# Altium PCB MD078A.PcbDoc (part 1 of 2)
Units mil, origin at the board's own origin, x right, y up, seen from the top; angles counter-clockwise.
Board outline 4255 x 2850 mil, 4 copper layers (Top Layer, Ground, Power, Bottom Layer), stack 61.6 mil thick; 156 components, 78 nets, 386 pads, 377 vias.
Unrouted connection lines stored in the file: 8.
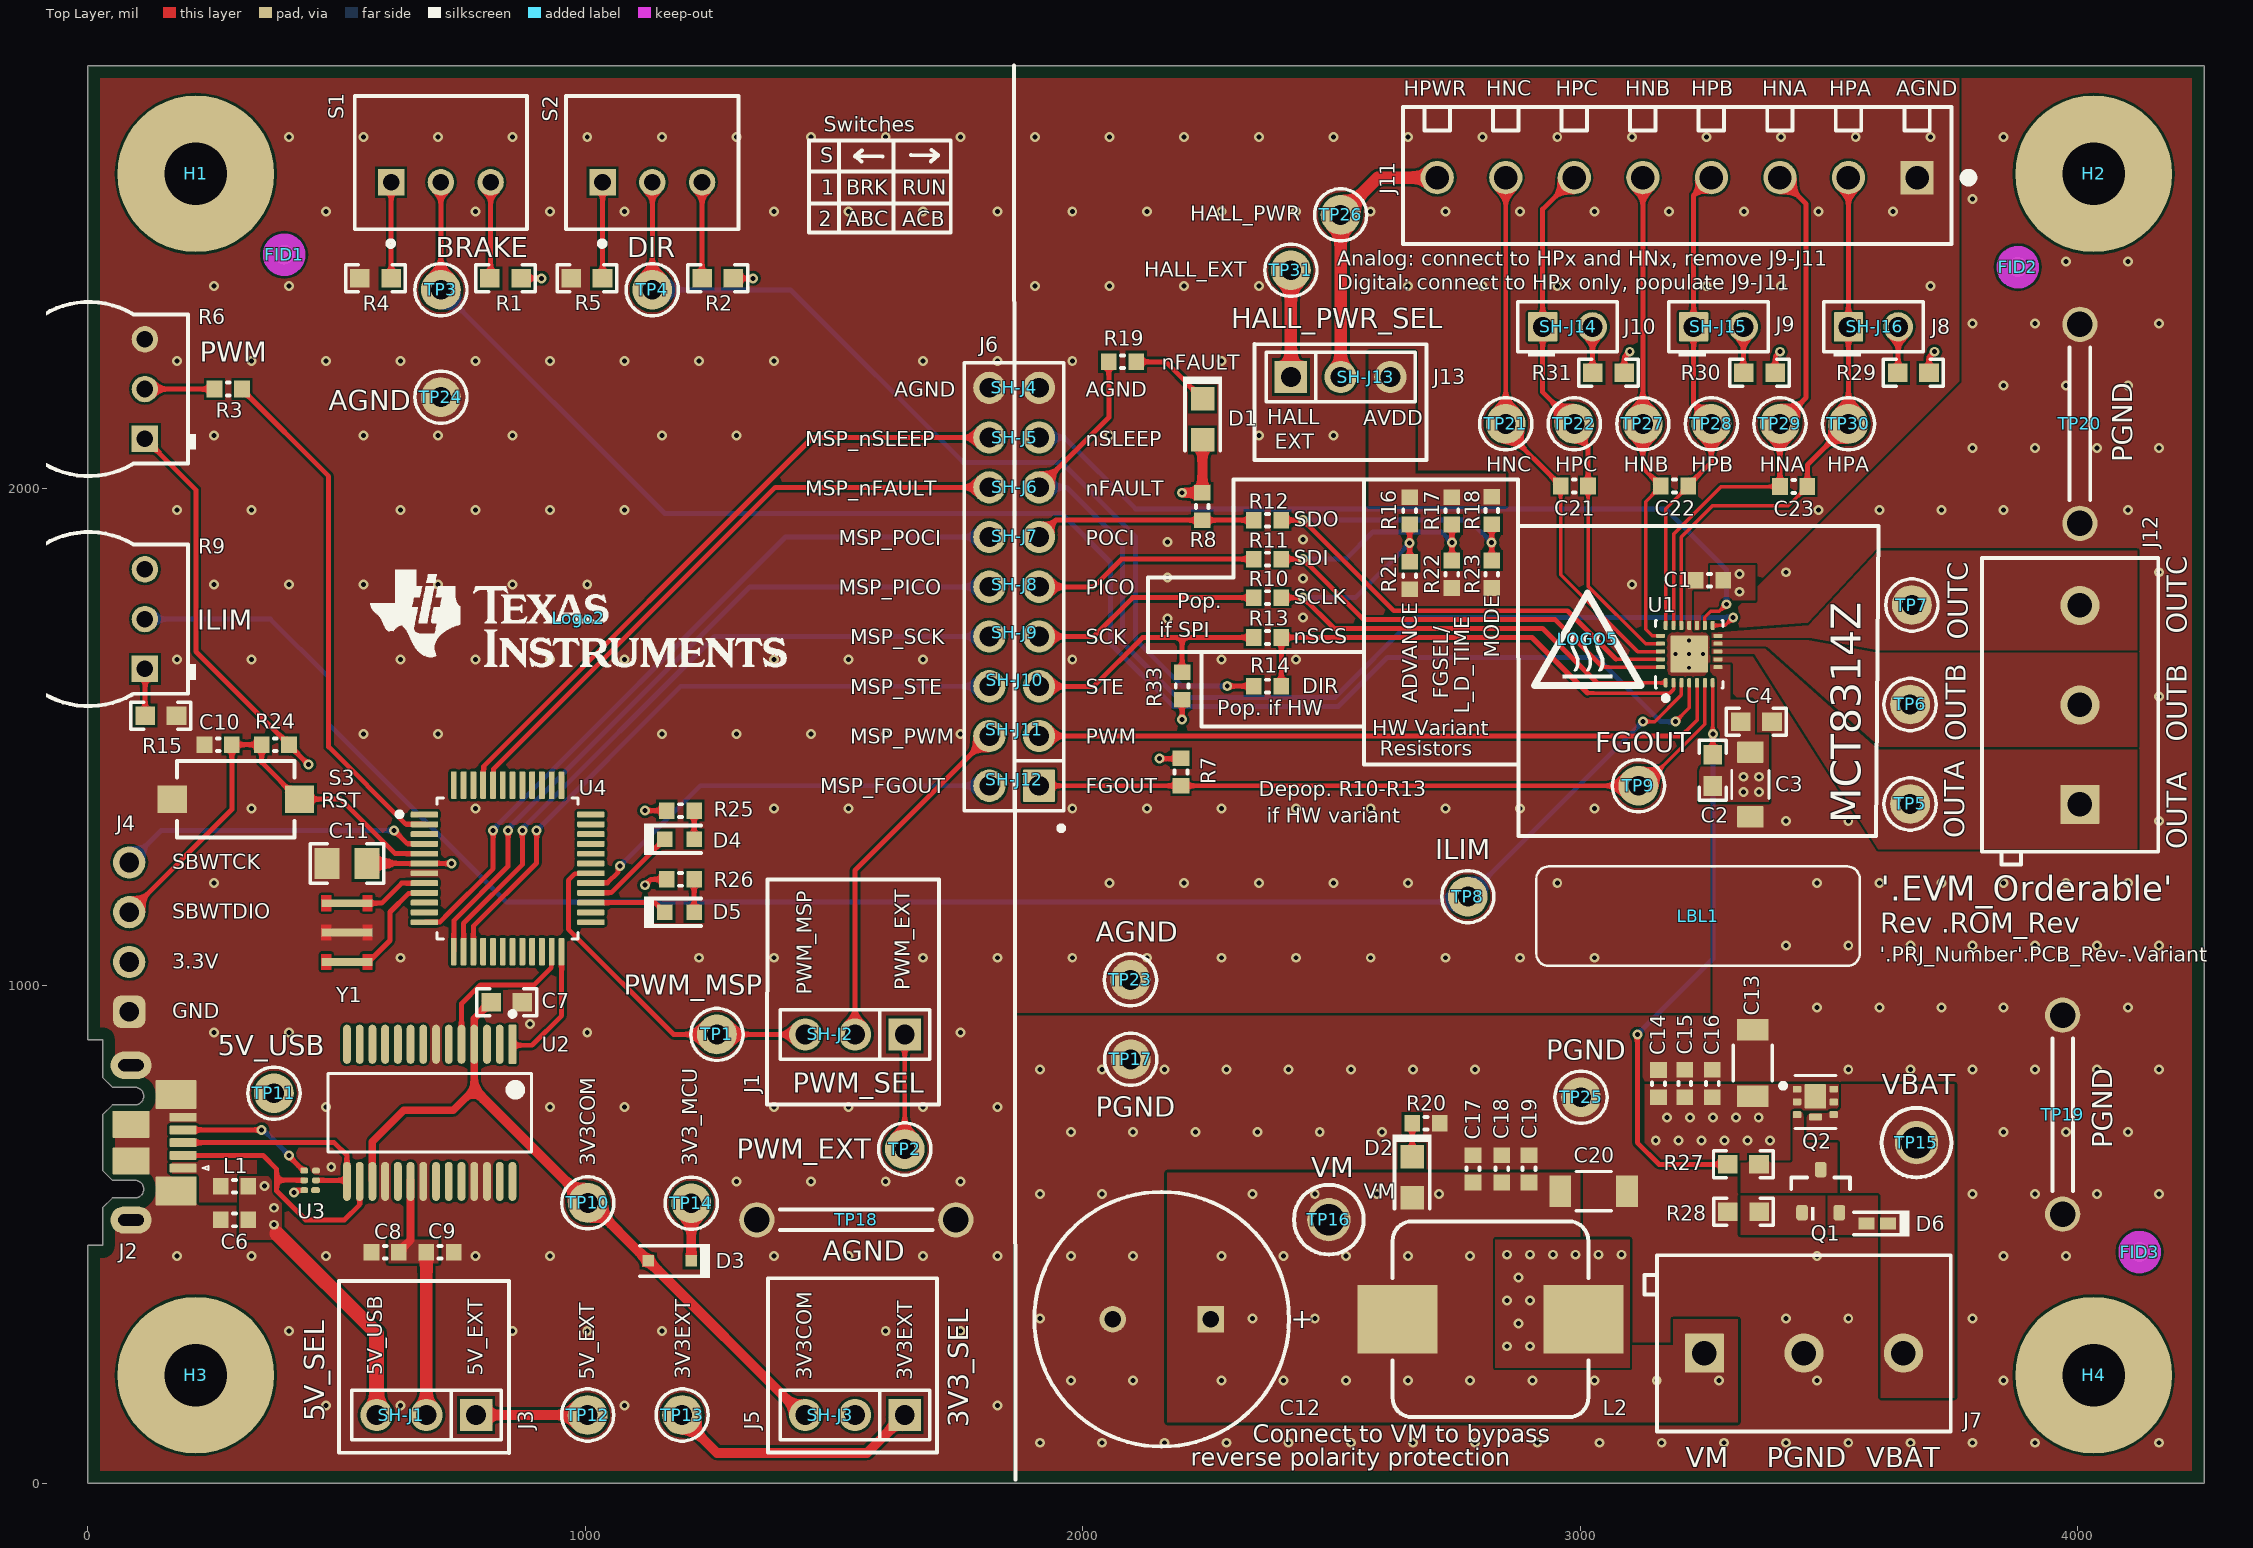
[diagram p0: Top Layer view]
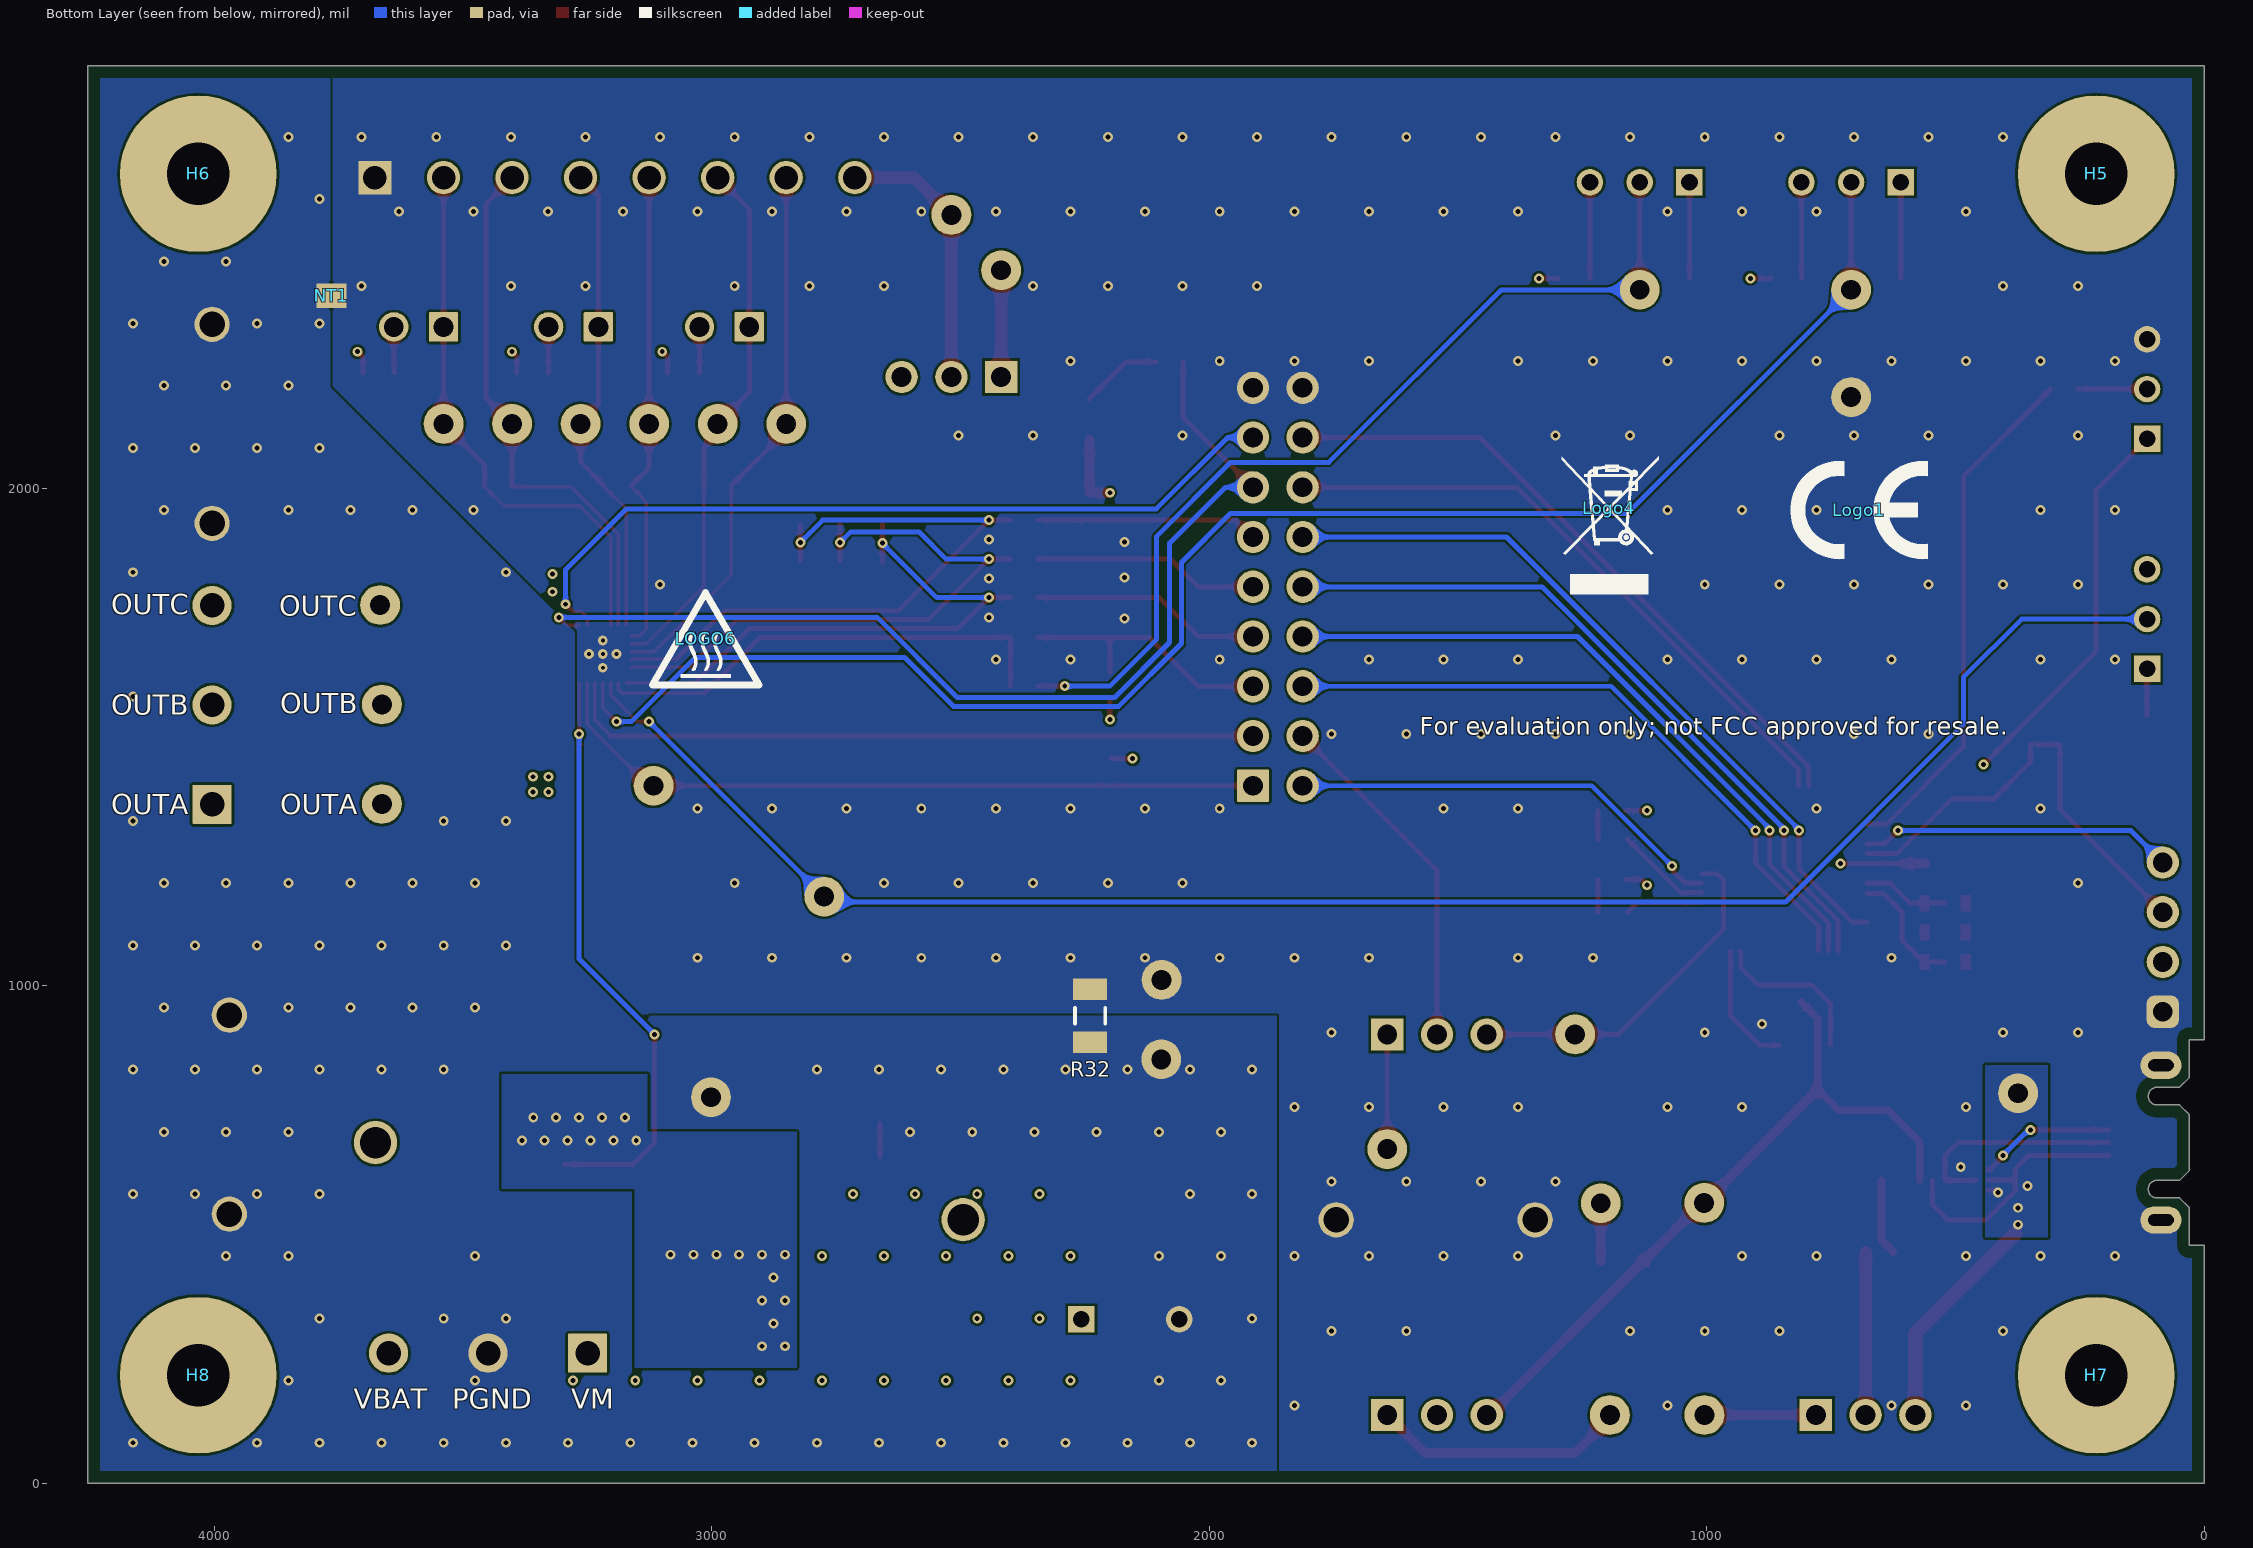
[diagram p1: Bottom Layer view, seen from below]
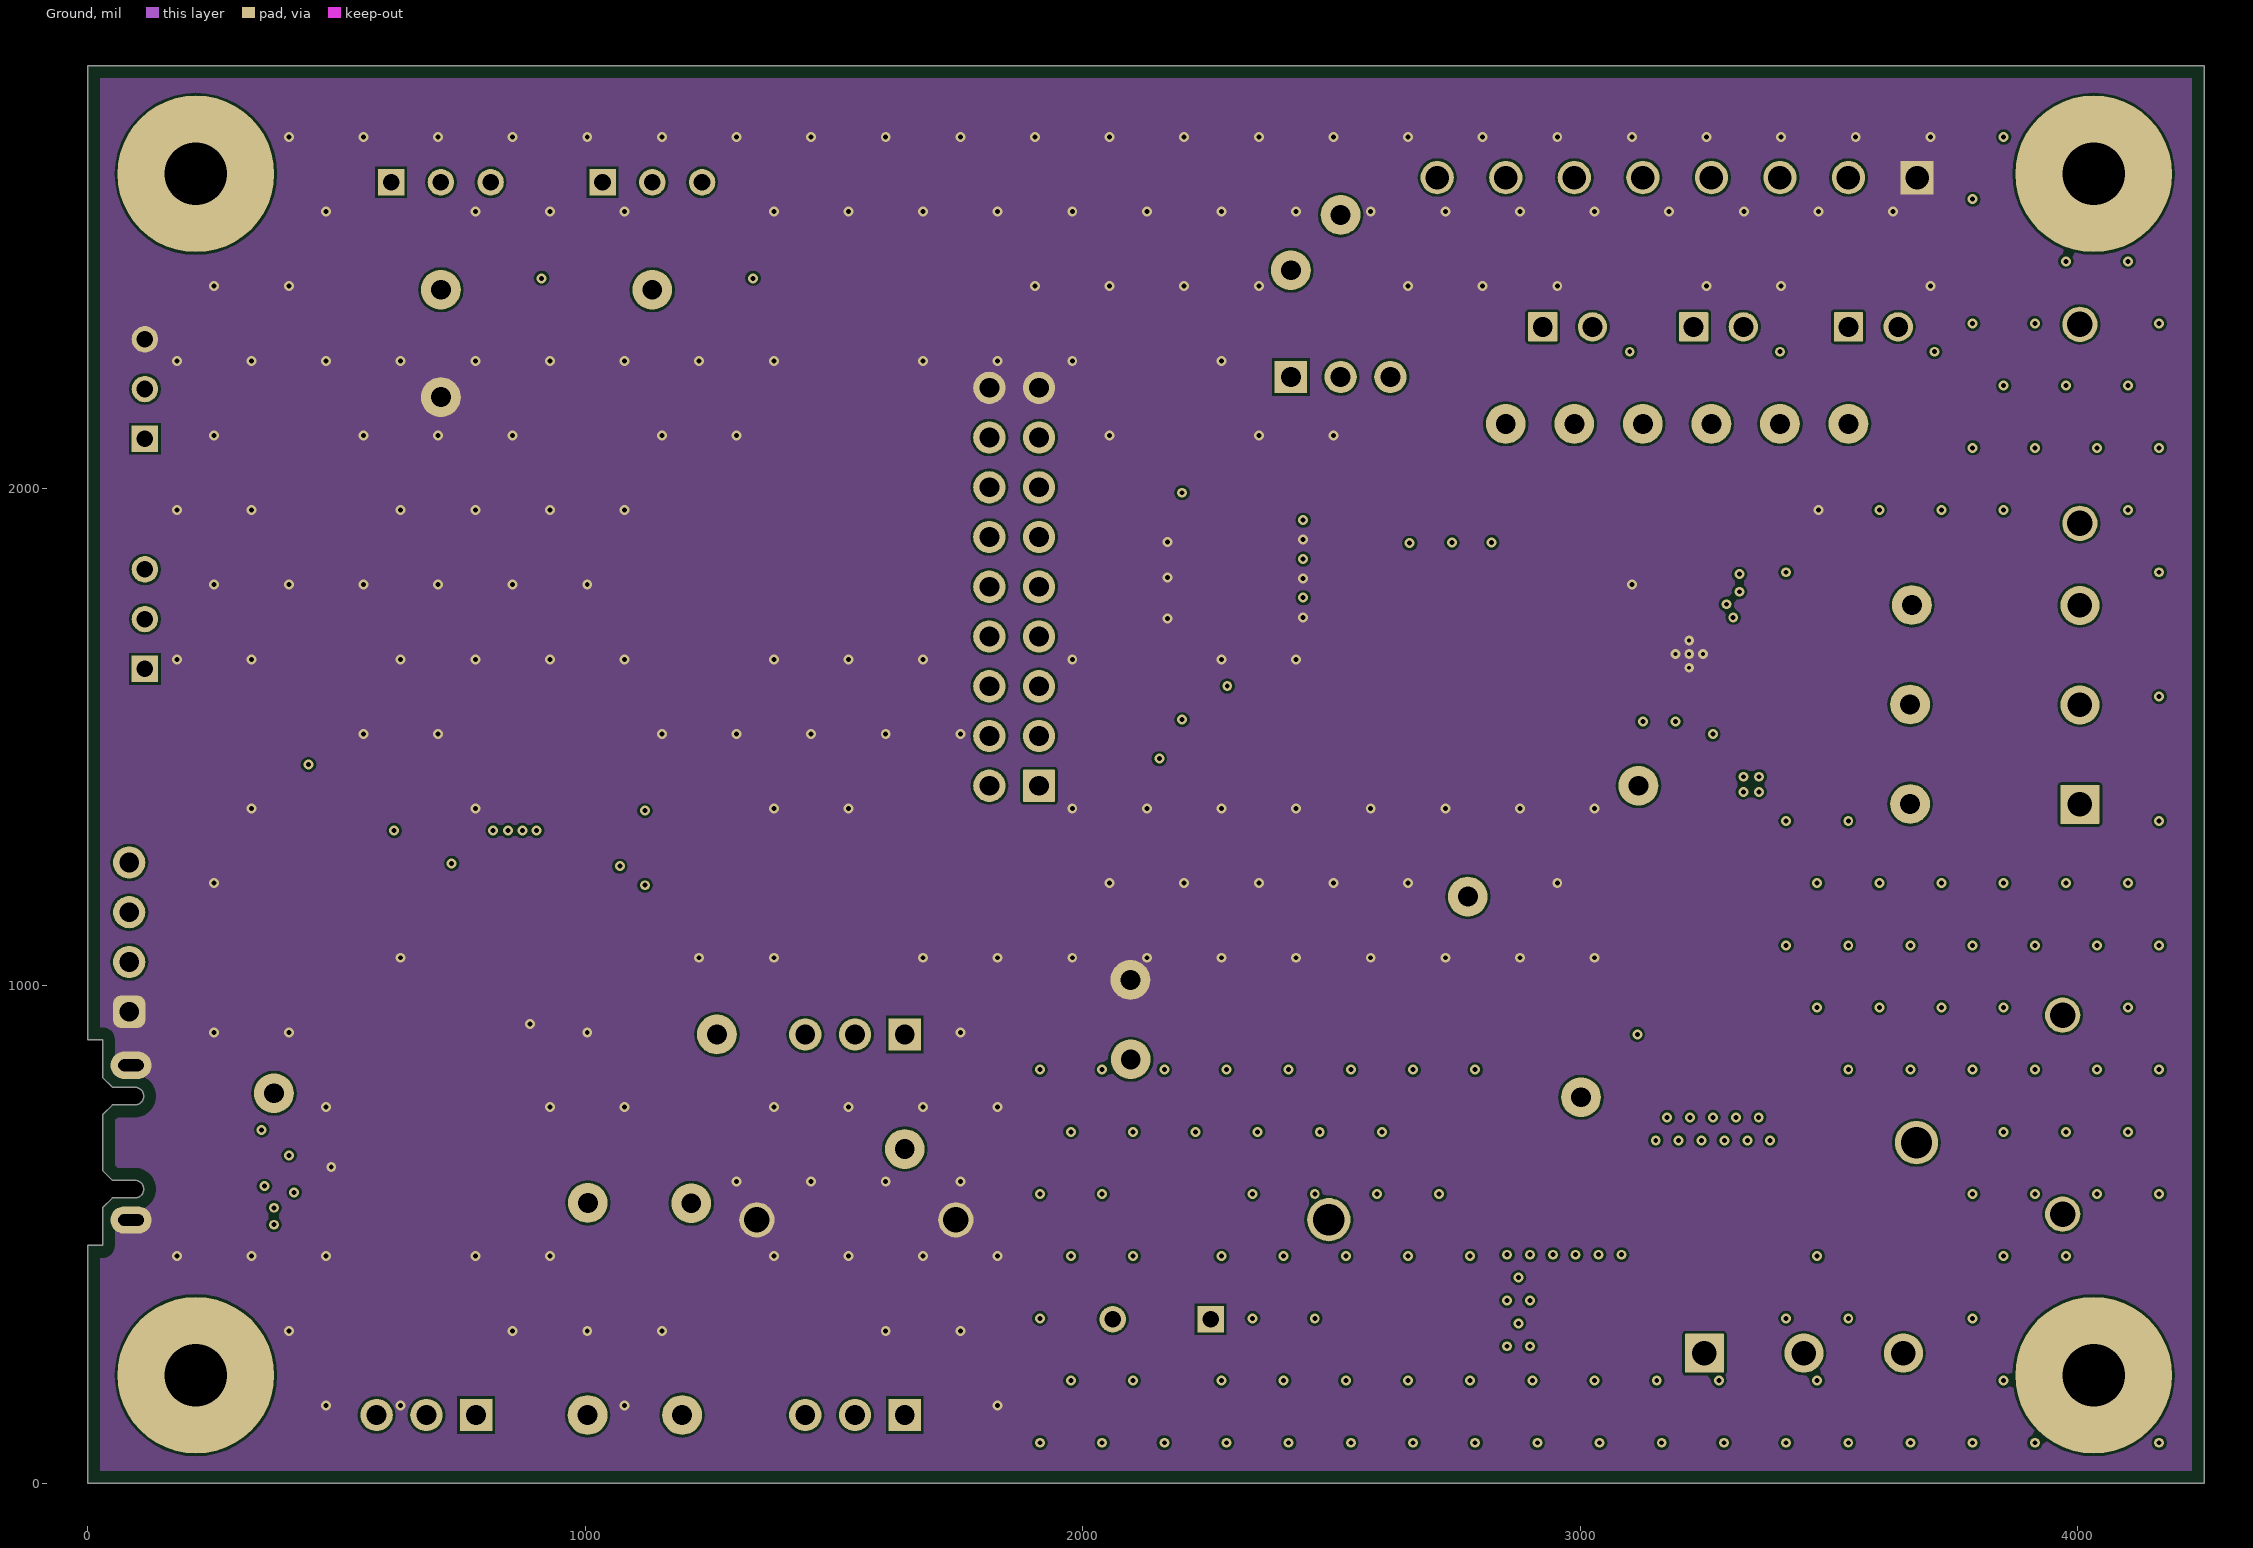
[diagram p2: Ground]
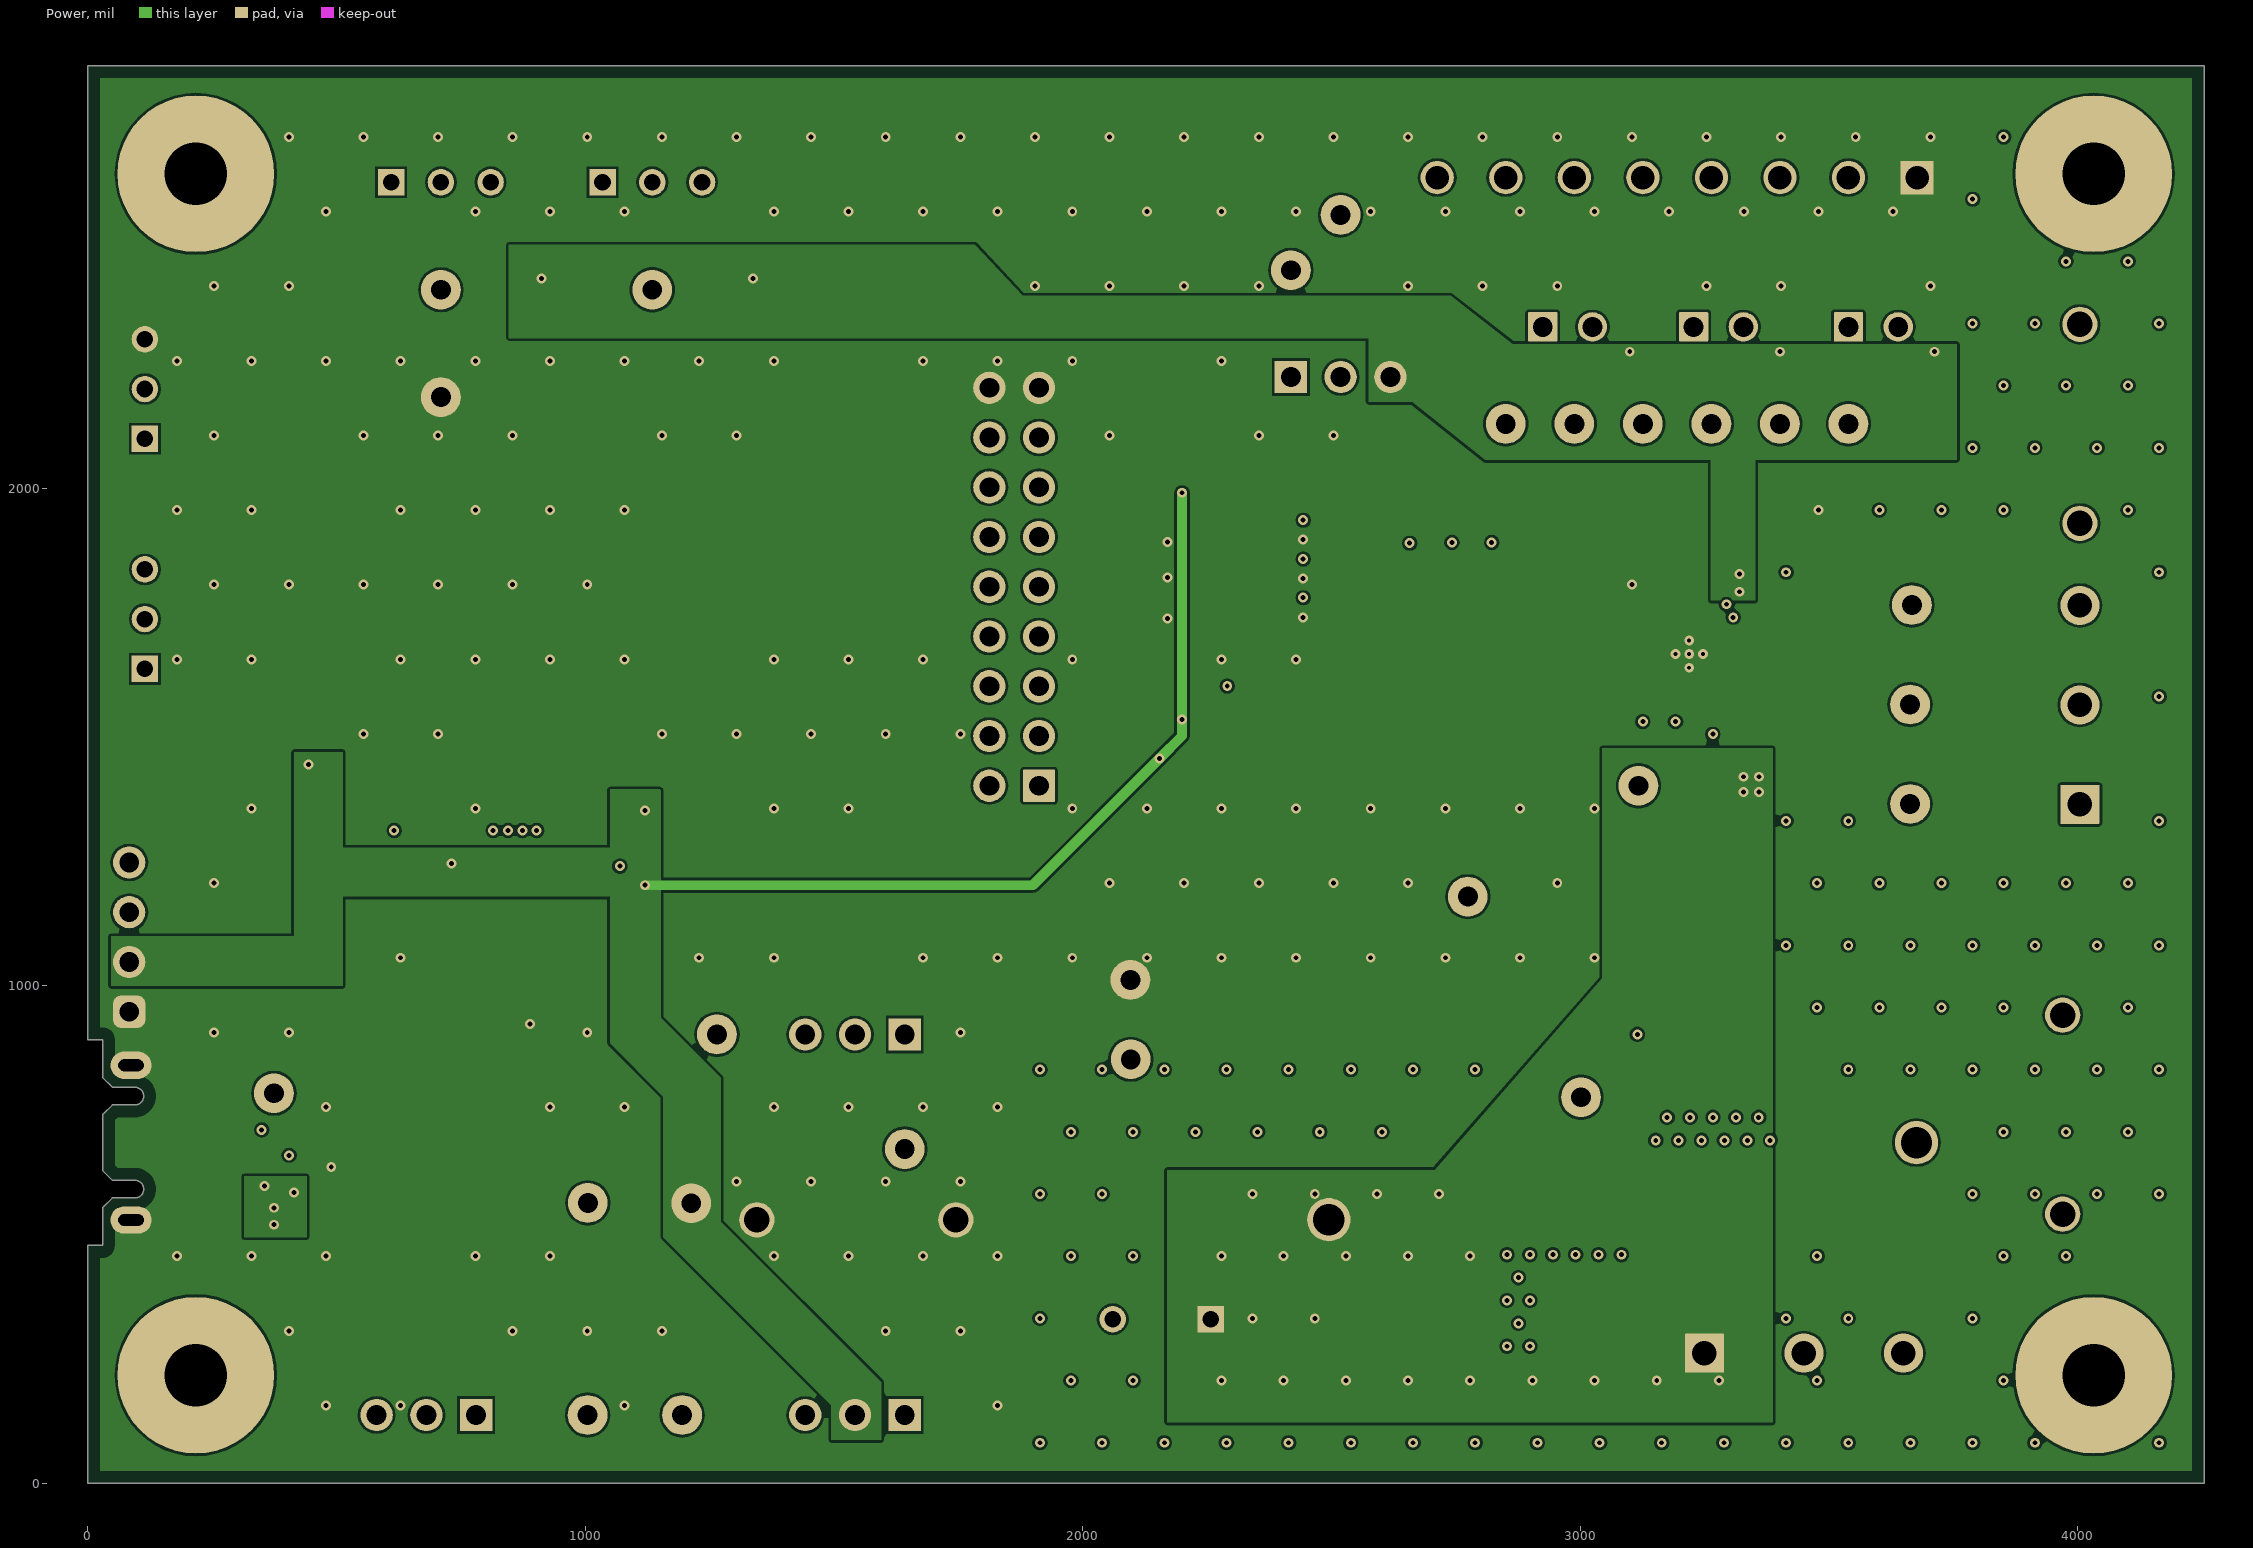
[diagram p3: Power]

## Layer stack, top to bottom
Top Solder: solder mask 0.4, Solder Resist, Dk 3.5
Top Layer: signal copper 1.4
Dielectric 1: prepreg 8, FR-4, Dk 4.2
Ground: signal copper 1.4
Dielectric 2: core 40, FR-4, Dk 4.2
Power: signal copper 1.4
Dielectric 3: prepreg 8, FR-4, Dk 4.2
Bottom Layer: signal copper 1.4
Bottom Solder: solder mask 0.4, Solder Resist, Dk 3.5

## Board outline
0,478.31 30,478.31 30,554.09 49.68,573.78 94.96,573.78 ccw(c94.85,591.5) 94.96,609.21 49.68,609.21 30,628.9 30,741.1 49.68,760.79 94.96,760.79 ccw(c94.85,778.5) 94.96,796.22 49.68,796.22 30,815.91 30,891.69 0,891.69 0,2850 4255,2850 4255,0 0,0

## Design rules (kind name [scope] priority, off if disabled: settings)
AcuteAngle [All] p1: minimum=4.50000000000000E+0001 checktracksonly=FALSE
AssemblyTestPointUsage [All] p1: valid=2
BoardOutlineClearance BoardOutlineClearance_1 [HasFootprint('Molex_1051640001')] p1: gap=0 ignorepadtopadclearanceinfootprint=FALSE
BoardOutlineClearance BoardOutlineClearance_MountingHoles [OnCopper and InComponentClass('Mounting Holes')] p2: gap=39.37 ignorepadtopadclearanceinfootprint=FALSE
BoardOutlineClearance BoardOutlineClearance_Poly [OnCopper and IsPoly] p3: gap=25 ignorepadtopadclearanceinfootprint=FALSE
BoardOutlineClearance [OnCopper and Not InComponentClass('Logo') and not InComponentClass('FiducialMark') and not InRegion(1000,500,4000,800) and not InPoly] p4: gap=30 ignorepadtopadclearanceinfootprint=FALSE
Clearance Clearance_Keepouts [((IsTrack Or IsArc) And Not InPoly) And IsFree and IsKeepOut vs ((IsTrack Or IsArc) And Not InPoly) And IsFree and IsKeepOut] p1: gap=0 ignorepadtopadclearanceinfootprint=FALSE
Clearance Clearance_Poly [InPolygon] p2: gap=5 ignorepadtopadclearanceinfootprint=TRUE
Clearance Clearance_FiducialMark [IsKeepOut and InComponentClass('FiducialMark') vs IsPad and InComponentClass('FiducialMark')] p3: gap=0 ignorepadtopadclearanceinfootprint=FALSE
Clearance [All] p4: gap=7.87 ignorepadtopadclearanceinfootprint=TRUE
ComponentClearance ComponentClearance_MountingHoles_FiducialMarks [InComponentClass('Mounting Holes') vs InComponentClass('FiducialMark')] p1: gap=50 collisioncheckmode=3 verticalgap=10 showdistances=FALSE
ComponentClearance ComponentClearance_Shunt [InComponentClass('Header') vs InComponentClass('Shunt')] p2: gap=0 collisioncheckmode=3 verticalgap=0 showdistances=FALSE
ComponentClearance ComponentClearance_Logo [InComponentClass('Logo')] p3: gap=50 collisioncheckmode=3 verticalgap=10 showdistances=FALSE
ComponentClearance ComponentClearance_ScrewToNut [(HasFootprint('NY PMS 440 0025 PH')) vs (HasFootprint('Keystone_1902C'))] p4: gap=5 collisioncheckmode=3 verticalgap=10 showdistances=FALSE
ComponentClearance ComponentClearance_MountingHoles [InComponentClass('Mounting Holes')] p5: gap=150 collisioncheckmode=3 verticalgap=100000 showdistances=FALSE
ComponentClearance ComponentClearance_SmallPassives [HasFootprint('0201*') or HasFootprint('0402*') or HasFootprint('0508') or HasFootprint('0603*') or HasFootprint('0612') or HasFootprint('0805*') or HasFootprint('0815*') or HasFootprint('0830*') or HasFootprint('1206*') or HasFootprint('1210*') or HasFootprint('1808*') or HasFootprint('1812*') or HasFootprint('1825*') or HasFootprint('2010*') or HasFootprint('2220*') or HasFootprint('2225*') or HasFootprint('2512*') or HasFootprint('2728*') or HasFootprint('3518*') vs HasFootprint('0201*') or HasFootprint('0402*') or HasFootprint('0508') or HasFootprint('0603*') or HasFootprint('0612') or HasFootprint('0805*') or HasFootprint('0815*') or HasFootprint('0830*') or HasFootprint('1206*') or HasFootprint('1210*') or HasFootprint('1808*') or HasFootprint('1812*') or HasFootprint('1825*') or HasFootprint('2010*') or HasFootprint('2220*') or HasFootprint('2225*') or HasFootprint('2512*') or HasFootprint('2728*') or HasFootprint('3518*')] p6: gap=14.96 collisioncheckmode=3 verticalgap=10 showdistances=FALSE
ComponentClearance ComponentClearance_THtoSMT [IsThruComponent vs IsSMTComponent] p7: gap=0 collisioncheckmode=3 verticalgap=0 showdistances=FALSE
ComponentClearance ComponentClearance_THtoTH [IsThruComponent vs IsThruComponent] p8: gap=0 collisioncheckmode=3 verticalgap=0 showdistances=FALSE
ComponentClearance [All] p9: gap=0 collisioncheckmode=3 verticalgap=0 showdistances=FALSE
DiffPairsRouting [All] p1: maxlimit=100 minlimit=10 mostfreqgap=10 toplayer_minwidth=10 toplayer_maxwidth=15 toplayer_prefwidth=15 midlayer1_minwidth=10 midlayer1_maxwidth=15 midlayer1_prefwidth=15 midlayer2_minwidth=10 midlayer2_maxwidth=15 midlayer2_prefwidth=15 bottomlayer_minwidth=10 bottomlayer_maxwidth=15 bottomlayer_prefwidth=15 maxuncoupledlength=1000
FabricationTestPointUsage TestPointUsage [All] p1: valid=2 allowmultiple=FALSE
FabricationTestpoint Testpoint [All] p1: side=3 testpointundercomponent=TRUE minsize=40 maxsize=100 preferedsize=60 minholesize=0 maxholesize=40 preferedholesize=32 testpointgrid=1 allowsidetop=TRUE allowsidebottom=TRUE usegrid=TRUE gridtolerance=0.01
FanoutControl Fanout_LCC [IsLCC] p1: bgadir=Out bgaviamode=Centered fanoutstyle=Auto fanoutdirection=Alternating viagrid=1 // Fanout_LCC (Default Rule)
FanoutControl Fanout_BGA [IsBGA] p2: bgadir=Out bgaviamode=Centered fanoutstyle=Auto fanoutdirection=Alternating viagrid=1 // Fanout_BGA (Default Rule)
FanoutControl Fanout_Default [All] p4: bgadir=Out bgaviamode=Centered fanoutstyle=Auto fanoutdirection=Alternating viagrid=1 // Fanout_Default (Default Rule)
FanoutControl Fanout_Small [(CompPinCount < 5)] p5: bgadir=Out bgaviamode=Centered fanoutstyle=Auto fanoutdirection=OutThenIn viagrid=1 // Fanout_Small (Default Rule)
HoleSize [All] p1: absolutevalues=TRUE maxlimit=200 minlimit=1 maxpercent=80.000 minpercent=20.000
MinimumAnnularRing MinimumAnnularRing_ThermalPadVias [IsVia and InAnyComponent] p1: minimumring=1
MinimumAnnularRing [All] p2: minimumring=1
MinimumSolderMaskSliver MinimumSolderMaskSliver_Logo [InComponentClass('Logo') vs InComponentClass('Logo')] p1: minsoldermaskwidth=0.7
MinimumSolderMaskSliver [All] p2: minsoldermaskwidth=1
PlaneConnect [All] p1: planeconnectstyle=Relief reliefexpansion=10 reliefentries=4 reliefconductorwidth=10 reliefairgap=10
PolygonConnect [All] p1: connectstyle=Direct reliefconductorwidth=10 reliefentries=4 polygonreliefangle="90 Angle" airgapwidth=10
RoutingVias ThermalPadVias [IsVia and InAnyComponent] p1: holewidth=7.87 width=19.68 viastyle="Through Hole" minholewidth=7.87 minwidth=19.68 maxholewidth=12.99 maxwidth=23.62
RoutingVias [All] p2: holewidth=10 width=25 viastyle="Through Hole" minholewidth=7 minwidth=20 maxholewidth=15 maxwidth=30
SilkToBoardRegionClearance [Not ((IsComment or IsDesignator) And (Hide <> 'False')) and not InRegion(1000,500,4000,800)] p1:
SilkToSilkClearance SilkToSilkClearance_Pb-FreeLogo [(HasFootprint('Pb-Free_Overlay_Medium') OR HasFootprint('Pb-Free_Overlay_Small')) vs (HasFootprint('Pb-Free_Overlay_Medium') OR HasFootprint('Pb-Free_Overlay_Small'))] p1: silktosilkclearance=1
SilkToSilkClearance [All] p2: silktosilkclearance=1
SilkToSolderMaskClearance [IsPad] p1: minsilkscreentomaskgap=1 clearancetoexposedcopper=TRUE
SolderMaskExpansion [All] p1: expansion=1.97 istentingtop=FALSE
UnRoutedNet [All] p1: checkbadconnections=TRUE
Width [All] p1: maxlimit=100 minlimit=6 preferedwidth=10 checkconnectedcopper=TRUE
14 further rules are at their usual default settings.

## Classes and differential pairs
component class Label: LBL1
component class "Mounting Holes": H1 H2 H3 H4
component class MD078A_INTERFACE: 3V3_EXT C6 C7 C8 C9 C10 C11 D3 D4 D5 J2 J3 J4 J5 J6 L1 R24 R25 R26 S3 SH-J2 SH-J3 SH-J4 SH-J5 SH-J6 SH-J7 SH-J8 SH-J9 SH-J10 SH-J11 SH-J12 TP10 TP11 TP12 TP13 TP14 U2 U3 U4 Y1
component class MD078A_CONTROL: J1 R1 R2 R3 R4 R5 R6 S1 S2 SH-J1 TP1 TP2 TP3 TP4
component class Shunt: SH-J1 SH-J2 SH-J3 SH-J4 SH-J5 SH-J6 SH-J7 SH-J8 SH-J9 SH-J10 SH-J11 SH-J12 SH-J13 SH-J14 SH-J15 SH-J16
component class MD078A_POWER_AND_CONNECTORS: AGND1 C12 C13 C14 C15 C16 C17 C18 C19 C20 C21 C22 C23 D6 J7 J8 J9 J10 J11 J12 J13 L2 NT1 PGND PGND2 Q1 Q2 R27 R28 R29 R30 R31 R32 R45 SH-J13 SH-J14 SH-J15 SH-J16 TP15 TP16 TP17 TP18 TP19 TP20 TP21 TP22 TP23 TP24 TP25 TP26 TP27 TP28 TP29 TP30 TP31 vm VM1
component class MD078A_DRIVER: 1 A1 B1 C1 C2 C3 C4 D1 D2 D? ILIM1 R7 R8 R9 R10 R11 R12 R13 R14 R15 R16 R17 R18 R19 R20 R21 R22 R23 R33 TP5 TP6 TP7 TP8 TP9 U1
component class Header: J1 J3 J4 J5 J6 J8 J9 J10 J13
component class Logo: Logo2
component class MD078A_HARDWARE: FID1 FID2 FID3 H1 H2 H3 H4 H5 H6 H7 H8 LBL1 Logo1 Logo2 Logo3 Logo4 LOGO5 LOGO6 ZZ1 ZZ2 ZZ3 ZZ4
component class FiducialMark: FID1 FID2 FID3
component class AssemblyNote: ZZ1 ZZ2 ZZ3 ZZ4

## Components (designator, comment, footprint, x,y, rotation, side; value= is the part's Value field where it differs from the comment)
C1 "GRM188Z71C225KE43" 0603L 3260.43,1815.47 r180 top value=2.2uF
C2 "C0603C224K4RACTU" 0603 3266.91,1433.54 r90 top value=0.22uF
C3 "C3216X6S2A106K160AC" FP-C3216X6S2A106K160AC_1206-MFG 3342.44,1405 r90 top value=10µF
C4 "GCJ188R72A104KA01D" 0603 3354.41,1531.45 r0 top value=0.1uF
C6 "C0603C104K8RACTU" 0603L 295.3,529.83 r180 top value=0.1uF
C7 "C0603C104K8RACTU" 0603 842.5,967.5 r0 top value=0.1uF
C8 "GRM188Z71A475ME15D" 0603L 597.93,464.83 r0 top value=4.7uF
C9 "C0603C104K8RACTU" 0603L 708.38,464.83 r0 top value=0.1uF
C10 "885012206034" 0603L 262.36,1485.08 r180 top value=1000pF
C11 "C0805C105K5RACTU" 0805_HV 521.16,1246.18 r180 top value=1uF
C12 "ELXZ630ELL331MK20S" Chemi-Con_1250x2000 2159.07,330 r180 top value=330uF
C13 "GRM31CR72A105KA01L" 1206_180 3347.22,845.06 r90 top value=1uF
C14 "CGA3E3X7S2A104K080AB" 0603L 3157.89,803.52 r90 top value=0.1uF
C15 "CGA3E2X7R2A103K080AA" 0603L 3210.43,803.77 r90 top value=0.01uF
C16 "06031C102JAT2A" 0603L 3266.18,803.88 r90 top value=1000pF
C17 "06031C102JAT2A" 0603L 2785,632.45 r90 top value=1000pF
C18 "CGA3E2X7R2A103K080AA" 0603L 2842.95,632.45 r90 top value=0.01uF
C19 "CGA3E3X7S2A104K080AB" 0603L 2897.5,632.45 r90 top value=0.1uF
C20 "GRM31CR72A105KA01L" 1206_180 3027.5,587.55 r0 top value=1uF
C21 "0603YC104K4T4A" 0603L 2988.52,2005 r0 top value=0.1uF
C22 "0603YC104K4T4A" 0603L 3189.74,2005 r0 top value=0.1uF
C23 "0603YC104K4T4A" 0603L 3429.47,2004.02 r0 top value=0.1uF
D1 "LTST-C170KRKT" LED_LTST-C170_Red 2241.38,2139.02 r90 top value=Red
D2 "LTST-C170KGKT" LTST-C170KGKT_Green 2662.52,615.11 r90 top value=Green
D3 "BAT165E6327HTSA1" SOD-323 1170,447.36 r180 top value=40V
D4 "LTST-C190KRKT" LED_LTST-C190_Red 1189.52,1295.15 r180 top value=Red
D5 "LTST-C190GKT" LED_LTST-C190 1189.52,1148.04 r180 top value=Green
D6 "BAS516,115" SOD-523 3597.5,522.5 r180 top value=100V
FID1 "Fiducial" Fiducial10-20 395,2470 r0 top
FID2 "Fiducial" Fiducial10-20 3880,2445 r0 top
FID3 "Fiducial" Fiducial10-20 4125,465 r0 top
H1 "NY PMS 440 0025 PH" "NY PMS 440 0025 PH" 217.5,2632.5 r0 top
H2 "NY PMS 440 0025 PH" "NY PMS 440 0025 PH" 4032.5,2632.5 r0 top
H3 "NY PMS 440 0025 PH" "NY PMS 440 0025 PH" 217.5,217.5 r0 top
H4 "NY PMS 440 0025 PH" "NY PMS 440 0025 PH" 4032.5,217.5 r0 top
H5 "Nut" Keystone_1902C 217.5,2632.5 r180 bottom
H6 "Nut" Keystone_1902C 4032.5,2632.5 r180 bottom
H7 "Nut" Keystone_1902C 217.5,217.5 r180 bottom
H8 "Nut" Keystone_1902C 4032.5,217.5 r180 bottom
J1 "Header_3x1" PBC03SAAN 1542.5,902.5 r180 top
J2 "1051640001" Molex_1051640001 30,685 r270 top
J3 "Header_3x1" PBC03SAAN 680.89,137.5 r180 top
J4 "TSW-104-07-G-S" TSW-104-07-G-S 83.45,1098.24 r90 top
J5 "Header_3x1" PBC03SAAN 1542.5,137.5 r180 top
J6 "TSW-109-07-G-D" Samtec_TSW-109-07-G-D 1862.5,1802.5 r90 top
J7 "MOTOR_OUT" On-Shore_ED120_3DS 3450,261.84 r0 top
J8 "PEC02SAAN" CONN_PEC02SAAN 3589.65,2325 r0 top
J9 "PEC02SAAN" CONN_PEC02SAAN 3278.33,2325 r0 top
J10 "PEC02SAAN" CONN_PEC02SAAN 2975,2325 r0 top
J11 "OSTTE080161" On-Shore_OSTTE080161 3195.22,2625 r180 top
J12 "MOTOR_OUT" On-Shore_ED120_3DS 4005,1565 r90 top
J13 "HALL_PWR_SEL" PBC03SAAN 2518.77,2224.15 r0 top
L1 "BLM18SG121TZ1D" 0603L 295,597.5 r180 top
L2 "SRP1038A-1R0M" SRP1038A 2820,330 r180 top value=1uH
LBL1 "THT-14-423-10" Label_650x200 3237.22,1140.32 r180 top
Logo1 "CE Mark" CE_Mark_5mm 694.08,1956.7 r180 bottom
Logo2 "Texas Instruments" TI_Stacked_Overlay_Small 986.72,1739.02 r0 top
Logo3 "FCC disclaimer" FCC_disclaimer 2440,3370 r90 top
Logo4 "WEEE logo" WEEE_Minimum 1196.35,1960.2 r180 bottom
LOGO5 "CAUTION HOT SURFACE" IEC_HotSurface_Small 3015.13,1697.29 r0 top
LOGO6 "CAUTION HOT SURFACE" IEC_HotSurface_Small 3012.63,1698.29 r180 bottom
NT1 "Net-Tie" Net-Tie_50milWide_30milLong 3765,2387.5 r0 bottom net-tie
Q1 "FMMT620TA" SOT-23L 3483.75,587.55 r90 top value="80 V"
Q2 "BUK9D23-40EX" FP-BUK9D23-40EX_SOT1220-MFG 3473.19,766.91 r0 top
R1 "RC0603FR-0710KL" 0603 840,2422.5 r0 top value=10.0k
R2 "RC0603FR-0710KL" 0603 1266.52,2422.52 r0 top value=10.0k
R3 "ERJ-3GEY0R00V" 0603L 282.5,2200 r180 top value=0
R4 "RC0603FR-0710KL" 0603 578.41,2422.48 r0 top value=10.0k
R5 "RC0603FR-0710KL" 0603 1003.46,2422.52 r0 top value=10.0k
R6 "3352T-1-253LF" Bourns_3352T 115,2200 r90 top value=25k
R7 "RC0603JR-075K1L" 0603L 2197.93,1430.13 r90 top value=5.1k
R8 "RC0603JR-075K1L" 0603L 2240.61,1963.92 r90 top value=5.1k
R9 "3352T-1-103LF" Bourns_3352T 115,1737.5 r90 top value=10kΩ
R10 "ERJ-3GEY0R00V" 0603L 2371.95,1780.64 r0 top value=0
R11 "ERJ-3GEY0R00V" 0603L 2371.95,1858.14 r0 top value=0
R12 "ERJ-3GEY0R00V" 0603L 2371.95,1936.33 r0 top value=0
R13 "ERJ-3GEY0R00V" 0603L 2371.95,1700.64 r0 top value=0
R14 "ERJ-3GEY0R00V" 0603L 2371.95,1602.81 r0 top value=0
R15 "RC0603JR-076K2L" 0603 147.01,1543.35 r180 top value=6.2k
R16 "ERA-3AEB104V" 0603L 2657.5,1955.2 r90 top value=100k
R17 "ERJ-3GEY0R00V" 0603L 2742.5,1955.2 r90 top value=0
R18 "ERJ-3EKF2202V" 0603L 2822.5,1955.7 r90 top value=22.0k
R19 "RC0603JR-071KL" 0603L 2080.24,2254.79 r0 top value=1.0k
R20 "RT0603BRD074K7L" 0603L 2690.28,724.11 r180 top value=4.70k
R21 "ERJ-3GEY0R00V" 0603L 2657.5,1824.94 r90 top value=0
R22 "ERJ-3GEY0R00V" 0603L 2742.5,1827.74 r90 top value=0
R23 "ERA-3AEB104V" 0603L 2822.5,1827.74 r90 top value=100k
R24 "RC0603JR-0747KL" 0603L 377.2,1485.08 r0 top value=47k
R25 "RC0603JR-07470RL" 0603L 1191.51,1352.5 r180 top value=470
R26 "RC0603JR-07470RL" 0603L 1191.51,1214.26 r180 top value=470
R27 "RC0603FR-0710KL" 0603 3328.33,641.48 r0 top value=10.0k
R28 "RC0603FR-0710KL" 0603 3328.5,545.84 r0 top value=10.0k
R29 "RC0603FR-0710KL" 0603 3670,2232.5 r180 top value=10.0k
R30 "RC0603FR-0710KL" 0603 3361,2232.5 r180 top value=10.0k
R31 "RC0603FR-0710KL" 0603 3057.5,2232.5 r180 top value=10.0k
R32 "RCA12060000ZSEA" 1206L 2240,940 r270 bottom value=0
R33 "RC0603JR-075K1L" 0603L 2200.05,1602.84 r270 top value=5.1k
S1 "SW_SPDT_COM2_1_3" SW_B12AP 710,2655 r90 top
S2 "SW_SPDT_COM2_1_3" SW_B12AP 1135,2655 r90 top
S3 "SW_SPST-single" SW_434121025816 297.8,1375.44 r180 top
SH-J1 "SNT-100-BK-G" SNT-100-BK-G 630,137.5 r180 top value=1x2
SH-J2 "SNT-100-BK-G" SNT-100-BK-G 1492.5,902.5 r180 top value=1x2
SH-J3 "SNT-100-BK-G" SNT-100-BK-G 1492.5,137.5 r180 top value=1x2
SH-J4 "SNT-100-BK-G" SNT-100-BK-G 1862.5,2202.5 r180 top value=1x2
SH-J5 "SNT-100-BK-G" SNT-100-BK-G 1863.16,2102.5 r180 top value=1x2
SH-J6 "SNT-100-BK-G" SNT-100-BK-G 1863.25,2002.5 r180 top value=1x2
SH-J7 "SNT-100-BK-G" SNT-100-BK-G 1863.33,1904 r180 top value=1x2
SH-J8 "SNT-100-BK-G" SNT-100-BK-G 1863.42,1806.72 r180 top value=1x2
SH-J9 "SNT-100-BK-G" SNT-100-BK-G 1863.5,1710.3 r180 top value=1x2
SH-J10 "SNT-100-BK-G" SNT-100-BK-G 1863.59,1615 r180 top value=1x2
SH-J11 "SNT-100-BK-G" SNT-100-BK-G 1862.5,1515 r180 top value=1x2
SH-J12 "SNT-100-BK-G" SNT-100-BK-G 1862.5,1415 r180 top value=1x2
SH-J13 "SNT-100-BK-G" SNT-100-BK-G 2569.13,2224.15 r180 top value=1x2
SH-J14 "SNT-100-BK-G" SNT-100-BK-G 2976.32,2325 r180 top value=1x2
SH-J15 "SNT-100-BK-G" SNT-100-BK-G 3277.5,2325 r180 top value=1x2
SH-J16 "SNT-100-BK-G" SNT-100-BK-G 3592.15,2325 r180 top value=1x2
TP1 "PWM_MSP" Keystone5002 1264.93,902.5 r90 top
TP2 "PWM_EXT" Keystone5002 1642.5,672.2 r90 top
TP3 "BRAKE" Keystone5002 710,2399.51 r90 top
TP4 "DIR" Keystone5002 1135,2399.51 r90 top
TP5 "OUTA" Keystone5000 3663.5,1365.83 r90 top
TP6 "OUTB" Keystone5000 3663.5,1565.83 r90 top
TP7 "OUTC" Keystone5000 3667.15,1765.83 r90 top
TP8 "ILIM" Keystone5002 2774.49,1179.63 r90 top
TP9 "FGOUT" Keystone5002 3117.48,1402.5 r90 top
TP10 "3V3COM" Keystone5000 1005.39,563.83 r90 top
TP11 "5V_USB" Keystone5000 374.4,784.37 r90 top
TP12 "5V_EXT" Keystone5000 1005.02,137.5 r90 top
TP13 "3V3EXT" Keystone5000 1195,137.5 r90 top
TP14 "3V3_MCU" Keystone5000 1213.31,563.23 r90 top
TP15 "VBAT" Keystone5005 3676.42,685 r180 top
TP16 "VM" Keystone5005 2495,530.11 r0 top
TP17 "PGND" Keystone5001 2096.74,852.5 r90 top
TP18 "AGND" Harwin_D3082-05 1545.19,529.83 r180 top
TP19 "PGND" Harwin_D3082-05 3970.19,741.32 r270 top
TP20 "PGND" Harwin_D3082-05 4005,2130 r90 top
TP21 "HNC" Keystone5002 2850.73,2130 r90 top
TP22 "HPC" Keystone5002 2988.52,2130 r90 top
TP23 "AGND" Keystone5001 2096.19,1012.13 r90 top
TP24 "AGND" Keystone5001 710,2183.75 r90 top
TP25 "PGND" Keystone5001 3002.02,776.25 r90 top
TP26 "HALL_PWR" Keystone5000 2518.77,2550 r90 top
TP27 "HNB" Keystone5002 3126.32,2130 r90 top
TP28 "HPB" Keystone5002 3264.11,2130 r90 top
TP29 "HNA" Keystone5002 3401.91,2130 r90 top
TP30 "HPA" Keystone5002 3539.65,2130 r270 top
TP31 "HALL_EXT" Keystone5000 2418.77,2438.75 r90 top
U1 "MCT8314Z0SRRWR" RRW0024A-MFG 3219.5,1667.2 r90 top
U2 "FT232RNL-REEL" FP-FT232RNL-REEL_SSOP28-MFG 687.5,745 r270 top
U3 "TPD4E004DRYR" DRY0006A 447.16,609.17 r180 top
U4 "MSP430FR2355TPTR" PT0048A-MFG 844.22,1236.34 r0 top
Y1 "CSTCR4M00G55B-R0" Murata_CSTCR_G 521.16,1107.3 r270 top
ZZ1 "This Assembly Note is for PCB labels only" AssemblyNoteLabel -593.73,3678.7 r0 top
ZZ2 "These assemblies are ESD sensitive, ESD precautions shall be observed." AssemblyNote -593.73,3569.82 r0 top
ZZ3 "These assemblies must be clean and free from flux and all contaminants. Use of no clean flux is not acceptable." AssemblyNote -593.73,3481.26 r0 top
ZZ4 "These assemblies must comply with workmanship standards IPC-A-610 Class 2, unless otherwise specified." AssemblyNote -593.73,3392.7 r0 top

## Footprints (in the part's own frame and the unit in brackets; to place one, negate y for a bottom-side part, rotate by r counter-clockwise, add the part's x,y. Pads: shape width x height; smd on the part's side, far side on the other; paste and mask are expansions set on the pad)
0603 [mm] "0603 from SM-752 data"
  rect 1x0.95 smd: 1(-0.8,0) 2(0.8,0)
  silkscreen extent -1.52,-0.69 1.52,0.69, body extent -0.87,-0.47 0.87,0.47, height 1
0603L [mm] "0603 from SM-752 data"
  rect 0.8x0.85 smd: 1(-0.7,0) 2(0.7,0)
  silkscreen extent -0.07,-0.33 0.07,0.33, body extent -0.87,-0.47 0.87,0.47, height 1
0805_HV [mil] "0805 with 30mil clearance between pads"
  rect 50x63 smd: 1(-40,0) 2(40,0)
  silkscreen extent -74,-40 74,40, body extent -43,-29 43,29, height 57
1206_180 [mm] "1206_180"
  rect 1.1x1.6 smd: 1(-1.7,0) 2(1.7,0)
  silkscreen extent -0.9,-1 0.9,1, body extent -1.75,-0.95 1.75,0.95, height 1.8
1206L [mm] "1206 from SM-752 data"
  rect 1.1x1.75 smd: 1(-1.35,0) 2(1.35,0)
  silkscreen extent -0.4,-0.77 0.4,0.77, body extent -1.7,-0.9 1.7,0.9, height 1.35
AssemblyNote [mil] "Assembly Note"
AssemblyNoteLabel [mil] "Assembly Note for PCB Labels"
Bourns_3352T [mm] "TH, 3-Leads, Body 9.53x8.89mm, Pitch 2.54mm"
  rect 1.35x1.35 hole 0.85: 1(-2.54,0)
  round 1.35 hole 0.85: 2(0,0) 3(2.54,0)
  silkscreen extent -4.44,-2.6 4.44,7.31, body extent -4.44,-2.21 4.45,7.32, height 3.81
CE_Mark_5mm [mil] "Minimum text height for CE Mark"
  silkscreen extent -138,-98 138,98
Chemi-Con_1250x2000 [mm] "TH, 2-Leads, Dia 12.5mm, Lead Sapcing 5mm"
  rect 1.35x1.35 hole 0.85: 1(-2.5,0)
  round 1.35 hole 0.85: 2(2.5,0)
  silkscreen extent -6.5,-6.5 6.5,6.5, body extent -6.5,-6.5 6.51,6.5, height 21.5
CONN_PEC02SAAN [mm] "SULLINS"
  rrect7% 1.5x1.5 hole 1.016: 1(-1.27,0)
  round 1.5 hole 1.016: 2(1.27,0)
  silkscreen extent -2.54,-1.52 2.54,1.27, body extent -2.54,-1.27 2.54,1.27, height 8.38
DRY0006A [mm] "USON-6"
  rrect67% 0.45x0.3 smd paste-0.05 mask-0.05: 1(-0.275,0.5)
  rrect67% 0.4x0.3 smd paste-0.05 mask-0.05: 2(-0.3,0) 3(-0.3,-0.5) 4(0.3,-0.5) 5(0.3,0) 6(0.3,0.5)
  body extent -0.5,-0.72 0.5,0.73, height 0.58
FCC_disclaimer [mil]
Fiducial10-20 [mm]
  round 1 smd mask+0.5: 1(0,0)
  Top Layer keep-out circle w1.178: c0,0 r0.5
FP-BUK9D23-40EX_SOT1220-MFG [mm]
  rrect29% 0.43x0.35 smd paste-1000 mask+0: 1(-0.935,0.65) 2(-0.935,0) 3(-0.935,-0.65) 4(0.935,-0.65) 5(0.935,0) 6(0.935,0.65)
  rrect9% 1.1x1.25 smd paste-1000 mask+0: 7(0,0.285)
  rrect29% 0.66x0.35 smd paste-1000 mask+0: 8(0,-0.775)
  silkscreen extent -1.77,-1.35 1.05,1.35, body extent -1.25,-1.15 1.25,1.15, height 0.25
FP-C3216X6S2A106K160AC_1206-MFG [mm]
  rrect9% 1.1x1.35 smd paste+0 mask+0: 1(-1.65,0) 2(1.65,0)
  silkscreen extent -0.72,-0.95 0.72,0.95, body extent -2.3,-1.05 2.3,1.05, height 0.25
FP-FT232RNL-REEL_SSOP28-MFG [mm]
  rrect25% 2x0.4 smd paste+0 mask+0: 1(-3.5,4.225)
  rrect100% 2x0.4 smd paste+0 mask+0: 2(-3.5,3.575) 3(-3.5,2.925) 4(-3.5,2.275) 5(-3.5,1.625) 6(-3.5,0.975) 7(-3.5,0.325) 8(-3.5,-0.325) 9(-3.5,-0.975) 10(-3.5,-1.625) 11(-3.5,-2.275) 12(-3.5,-2.925) 13(-3.5,-3.575) 14(-3.5,-4.225) 15(3.5,-4.225) 16(3.5,-3.575) 17(3.5,-2.925) 18(3.5,-2.275) 19(3.5,-1.625) 20(3.5,-0.975) 21(3.5,-0.325) 22(3.5,0.325) 23(3.5,0.975) 24(3.5,1.625) 25(3.5,2.275) 26(3.5,2.925) 27(3.5,3.575) 28(3.5,4.225)
  silkscreen extent -5.17,-5.2 2,5.2, body extent -4.6,-5.3 4.6,5.3, height 0.25
Harwin_D3082-05 [mm] "Shorting Plug, 10.16mm spacing, TH"
  round 1.8 hole 1.3: 1(-5.08,0) 2(5.08,0)
  silkscreen extent -3.9,-0.53 3.9,0.53, body extent -5.6,-0.52 5.61,0.52, height 6.63
IEC_HotSurface_Small [mil]
  silkscreen extent -107,-93 107,92
Keystone5000 [mil] "For Keystone 500x miniature loop terminals"
  round 80 hole 40: 1(0,0)
  silkscreen extent -52,-52 52,52, body extent -49,-49 49,49, height 182
Keystone5001 [mil] "For Keystone 500x miniature loop terminals"
  round 80 hole 40: 1(0,0)
  silkscreen extent -52,-52 52,52, body extent -49,-49 49,49, height 182
Keystone5002 [mil] "For Keystone 500x miniature loop terminals"
  round 80 hole 40: 1(0,0)
  silkscreen extent -52,-52 52,52, body extent -49,-49 49,49, height 182
Keystone5005 [mil] "Keystone Compact loops"
  round 87 hole 63: 1(0,0)
  silkscreen extent -70,-70 70,70, body extent -63,-63 62,63, height 225
Keystone_1902C [mil] "Hex Standoff, 4-40 threaded, nylon"
  round 1 on Mech4: 0(0,0)
  body extent -145,-126 146,126, height 501
Label_650x200 [mil] "Thermal Transfer Label"
  round 1 on Mech13: 0(0,0)
  silkscreen extent -325,-100 325,100, body extent -325,-100 325,100, height 1
LED_LTST-C170_Red [mm] "LITE-ON"
  rect 1.2x1.2 smd: 1(-1.05,0) 2(1.05,0)
  silkscreen extent -1.6,-1 2.2,1, body extent -1.05,-0.67 1.05,0.67, height 1.1
LED_LTST-C190 [mm] "Lite-On"
  rect 0.8x0.8 smd: 1(-0.75,0) 2(0.75,0)
  silkscreen extent -1.1,-0.8 1.8,0.8, body extent -0.85,-0.45 0.85,0.45, height 0.9
LED_LTST-C190_Red [mm] "Lite-On"
  rect 0.8x0.8 smd: 1(-0.75,0) 2(0.75,0)
  silkscreen extent -1.1,-0.8 1.8,0.8, body extent -0.85,-0.45 0.85,0.45, height 0.9
LTST-C170KGKT_Green [mm] "LITE-ON"
  rect 1.2x1.2 smd: 1(-1.05,0) 2(1.05,0)
  silkscreen extent -1.6,-1 2.2,1, body extent -1.05,-0.67 1.05,0.67, height 1.1
Molex_1051640001 [mm] "Receptacle, USB 2.0, Micro B, 5 Pos, 0.65mm Pitch, R/A, SMT"
  rrect22% 0.45x1.38 smd: 1(1.3,4.11) 2(0.65,4.11) 3(0,4.11) 4(-0.65,4.11) 5(-1.3,4.11)
  rrect7% 1.475x2.1 smd: 6(-2.462,3.75) 11(2.462,3.75)
  rrect100% 1.4x2.1 hole 0.6 slot 1.3 at 90 deg: 7(-3.95,1.45) 10(3.95,1.45)
  rrect7% 1.375x1.9 smd: 8(-0.937,1.45) 9(0.937,1.45)
  silkscreen extent 1.2,5.1 1.4,5.4, body extent -4.1,-0.7 4.1,4.47, height 2.45
Murata_CSTCR_G [mm] "Murata"
  rect 0.4x2.6 smd: 1(-1.5,0) 2(0,0) 3(1.5,0)
  Top Layer region: -0.4,0.8 0.4,0.8 0.4,1.3 -0.4,1.3
  Top Layer region: -0.4,-1.301 -0.4,-0.801 0.4,-0.801 0.4,-1.301
  Top Layer region: -1.9,0.8 -1.1,0.8 -1.1,1.3 -1.9,1.3
  Top Layer region: -1.9,-1.301 -1.9,-0.801 -1.1,-0.801 -1.1,-1.301
  Top Layer region: 1.1,0.8 1.9,0.8 1.9,1.3 1.1,1.3
  Top Layer region: 1.1,-1.301 1.1,-0.801 1.9,-0.801 1.9,-1.301
  body extent -2.25,-1 2.25,1, height 1.16
Net-Tie_50milWide_30milLong [mil] "50mil net tie, no solder mask opening, no solder paste"
  rect 30x50 smd paste-20 mask-20: 1(-15,0) 2(15,0)
"NY PMS 440 0025 PH" [mm] "4-40 nylon screw and mounting hole"
  round 8 hole 3.2: 1(0,0)
  body extent -3.3,-3.3 3.3,3.3, height 2.69
On-Shore_ED120_3DS [mm] "ONSHORE"
  rrect5% 2x2 hole 1.25: 1(-5.08,0)
  round 2 hole 1.25: 2(0,0) 3(5.08,0)
  silkscreen extent -8.14,-4 7.5,5, body extent -8.32,-4 7.62,5, height 13
On-Shore_OSTTE080161 [mm] "Term Blk 8x1"
  rect 1.7x1.7 hole 1.2: 1(-12.25,0)
  round 1.7 hole 1.2: 2(-8.75,0) 3(-5.25,0) 4(-1.75,0) 5(1.75,0) 6(5.25,0) 7(8.75,0) 8(12.25,0)
  silkscreen extent -14.98,-3.6 14,3.4, body extent -14,-3.6 14,3.4, height 8.4
PBC03SAAN [mm] "Sullins 100mil, 1x3, 230 mil above insulator"
  rect 1.65x1.65 hole 1.016: 1(-2.54,0)
  round 1.65 hole 1.016: 2(0,0) 3(2.54,0)
  silkscreen extent -3.81,-1.27 3.81,1.27, body extent -3.81,-1.27 3.81,1.27, height 8.38
PT0048A-MFG [mm]
  rrect33% 1.4x0.3 smd paste-1000 mask+0: 1(-4.25,2.75) 2(-4.25,2.25) 3(-4.25,1.75) 4(-4.25,1.25) 5(-4.25,0.75) 6(-4.25,0.25) 7(-4.25,-0.25) 8(-4.25,-0.75) 9(-4.25,-1.25) 10(-4.25,-1.75) 11(-4.25,-2.25) 12(-4.25,-2.75) 25(4.25,-2.75) 26(4.25,-2.25) 27(4.25,-1.75) 28(4.25,-1.25) 29(4.25,-0.75) 30(4.25,-0.25) 31(4.25,0.25) 32(4.25,0.75) 33(4.25,1.25) 34(4.25,1.75) 35(4.25,2.25) 36(4.25,2.75)
  rrect33% 0.3x1.4 smd paste-1000 mask+0: 13(-2.75,-4.25) 14(-2.25,-4.25) 15(-1.75,-4.25) 16(-1.25,-4.25) 17(-0.75,-4.25) 18(-0.25,-4.25) 19(0.25,-4.25) 20(0.75,-4.25) 21(1.25,-4.25) 22(1.75,-4.25) 23(2.25,-4.25) 24(2.75,-4.25) 37(2.75,4.25) 38(2.25,4.25) 39(1.75,4.25) 40(1.25,4.25) 41(0.75,4.25) 42(0.25,4.25) 43(-0.25,4.25) 44(-0.75,4.25) 45(-1.25,4.25) 46(-1.75,4.25) 47(-2.25,4.25) 48(-2.75,4.25)
  silkscreen extent -5.65,-3.6 3.6,3.6, body extent -5.05,-5.05 5.05,5.05, height 0.25
RRW0024A-MFG [mm]
  rrect50% 0.47x0.2 smd paste+0 mask+0: 1(-1.465,1.2) 2(-1.465,0.8) 3(-1.465,0.4) 4(-1.465,0) 5(-1.465,-0.4) 6(-1.465,-0.8) 7(-1.465,-1.2) 13(1.465,-1.2) 14(1.465,-0.8) 15(1.465,-0.4) 16(1.465,0) 17(1.465,0.4) 18(1.465,0.8) 19(1.465,1.2)
  rrect50% 0.2x0.47 smd paste+0 mask+0: 8(-0.67,-1.465) 9(-0.27,-1.465) 10(0.13,-1.465) 11(0.53,-1.465) 12(0.93,-1.465) 20(0.93,1.465) 21(0.53,1.465) 22(0.13,1.465) 23(-0.27,1.465) 24(-0.67,1.465)
  rrect5% 1.9x1.9 smd paste-1000 mask+0: 25(0,0)
  silkscreen extent -2.37,-1.73 1.73,1.73, body extent -1.8,-1.8 1.8,1.8, height 0.25
Samtec_TSW-109-07-G-D [mm] "Samtec 100mil, 2x9, 230 mil above insulator"
  rrect6% 1.65x1.65 hole 1.016: 1(-10.16,-1.27)
  round 1.65 hole 1.016: 2(-10.16,1.27) 3(-7.62,-1.27) 4(-7.62,1.27) 5(-5.08,-1.27) 6(-5.08,1.27) 7(-2.54,-1.27) 8(-2.54,1.27) 9(0,-1.27) 10(0,1.27) 11(2.54,-1.27) 12(2.54,1.27) 13(5.08,-1.27) 14(5.08,1.27) 15(7.62,-1.27) 16(7.62,1.27) 17(10.16,-1.27) 18(10.16,1.27)
  silkscreen extent -12.45,-2.54 11.43,2.54, body extent -11.43,-2.54 11.43,2.54, height 8.38
SNT-100-BK-G [mil] "Samtec STEP model"
  round 1 on Mech3: 0(0,0)
  body extent -100,-50 100,50, height 344
SOD-323 [mm] "NXP recommended land pattern"
  rect 0.6x0.6 smd paste-0.05: 1(-1.1,0) 2(1.1,0)
  silkscreen extent -2.06,-0.86 1.53,0.86, body extent -1.3,-0.67 1.3,0.68, height 1.1
SOD-523 [mm] "NXP Semiconductor recommended land pattern, nominal STEP model"
  rect 0.8x0.6 smd paste-0.05: 1(-0.55,0) 2(0.55,0)
  silkscreen extent -1.65,-0.66 1.2,0.66, body extent -0.8,-0.4 0.8,0.4, height 0.72
SOT-23L [mm] "SOT23, 3-Leads, Body 2.9x1.3mm, Pitch 0.95mm, Lead Span 2.5mm, IPC High Density"
  rrect50% 0.8x0.6 smd: 1(-1.1,0.95) 2(-1.1,-0.95) 3(1.1,0)
  silkscreen extent -1.5,-1.5 0.7,1.5, body extent -1.16,-1.45 1.21,1.45, height 1
SRP1038A [mm] "SMD, 2-Leads, Body 11x10mm"
  rect 4.1x3.5 smd: 1(-4.75,0) 2(4.75,0)
  silkscreen extent -5,-5 5,5, body extent -5.2,-5 5.2,5, height 3.75
SW_434121025816 [mm] "SMD, 2-Leads, Body 6x3.9mm, Pitch 6.5mm"
  rect 1.5x1.4 smd: 1(-3.25,0) 2(3.25,0)
  silkscreen extent -3,-1.95 3,1.95, body extent -3.65,-1.95 3.65,1.95, height 2.5
SW_B12AP [mm] "NKK Switches"
  rect 1.35x1.35 hole 0.85 paste-2539.97: 1(-1,2.54)
  round 1.35 hole 0.85 paste-2539.97: 2(-1,0) 3(-1,-2.54)
  silkscreen extent -4.27,-4.4 3.4,4.4, body extent -3.4,-4.39 3.4,4.39, height 22.87
TI_Stacked_Overlay_Small [mil]
  silkscreen extent -418,-98 418,98
TSW-104-07-G-S [mm] "Samtec 100mil, 1x4, 230 mil above insulator"
  rrect50% 1.65x1.65 hole 1.016: 1(-3.81,0)
  round 1.65 hole 1.016: 2(-1.27,0) 3(1.27,0) 4(3.81,0)
  body extent -5.08,-1.27 5.08,1.27, height 8.38
WEEE_Minimum [mil] "WEEElie bin"
  silkscreen extent -95,-172 99,104

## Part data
C1: library part CMP-0007499-4, "CAP, CERM, 2.2 uF, 16 V, +/- 10%, X7R, 0603", Cap_Case=0603, Manufacturer=MuRata, Supplier Part Number 1=81-GRM188Z71C225KE3D, TempCo=X7R, Tolerance_%=10%, Value1=Unknown, Value2=16V, ValueDisplayed=2.2uF
C2: library part CMP-0006903-4, "CAP, CERM, 0.22 uF, 16 V, +/- 10%, X7R, 0603", Cap_Case=0603, Manufacturer=Kemet, Supplier Part Number 1=399-5619-1-ND, TempCo=X7R, Tolerance_%=10%, Value1=Unknown, Value2=16V, ValueDisplayed=0.22uF
C3: library part CMP-0098402-1, "10 µF ±10% 100V Ceramic Capacitor X6S 1206 (3216 Metric)", Digikey Part Number=445-C3216X6S2A106K160ACCT-ND, Manufacturer=TDK, Mouser Part Number=810-C3216X6S2A106K16, Operating Temperature Range="-55°C to +105°C", TempCo=22%, Temperature Characteristic=X6S, Tolerance_%=10%, ValueDisplayed=10uF
C4: library part CMP-0064935-4, "CAP, CERM, 0.1 uF, 100 V,+/- 10%, X7R, AEC-Q200 Grade 1, 0603", Cap_Case=0603, Manufacturer=MuRata, Supplier Part Number 1=490-13420-1-ND, TempCo=X7R, Tolerance_%=10%, Value1=Unknown, Value2=100V, ValueDisplayed=0.1uF
C6 C7 C9: library part CMP-0006862-5, "CAP, CERM, 0.1 uF, 10 V, +/- 10%, X7R, 0603", Cap_Case=0603, Manufacturer=Kemet, Supplier Part Number 1=399-1095-1-ND, TempCo=X7R, Tolerance_%=10%, Value1=Unknown, Value2=10V, ValueDisplayed=0.1uF
C8: library part CMP-0007498-4, "CAP, CERM, 4.7 uF, 10 V, +/- 20%, X7R, 0603", Cap_Case=0603, Manufacturer=MuRata, TempCo=X7R, Tolerance_%=20%, Value1=Unknown, Value2=10V, ValueDisplayed=4.7uF
C10: library part CMP-0006826-4, "CAP, CERM, 1000 pF, 16 V, +/- 10%, X7R, 0603", Cap_Case=0603, Manufacturer="Wurth Elektronik", Supplier Part Number 1=710-885012206034, TempCo=X7R, Tolerance_%=10%, Value1=Unknown, Value2=16V, ValueDisplayed=1000pF
C11: library part CMP-0007730-2, "CAP, CERM, 1 uF, 50 V, +/- 10%, X7R, 0805", Cap_Case=0805, Manufacturer=Kemet, Supplier Part Number 1=399-7409-1-ND, TempCo=X7R, Tolerance_%=10%, Value1=Unknown, Value2=50V, ValueDisplayed=1uF
C12: library part CMP-0009912-2, "CAP, AL, 330 uF, 63 V, +/- 20%, AEC-Q200 Grade 2, TH", Cap_Case=12.5x20mm, Manufacturer=Chemi-Con, Supplier Part Number 1=565-2043-ND, Tolerance_%=20%, Value1=Unknown, Value2=63V, ValueDisplayed=330uF
C13 C20: library part CMP-0008970-2, "CAP, CERM, 1 uF, 100 V, +/- 10%, X7R, 1206", Cap_Case=2220, Manufacturer=MuRata, Supplier Part Number 1=490-3909-1-ND, TempCo=X7R, Tolerance_%=10%, Value1=Unknown, Value2=100V, ValueDisplayed=1uF
C14 C19: library part CMP-0007099-4, "CAP, CERM, 0.1 uF, 100 V, +/- 10%, X7S, AEC-Q200 Grade 1, 0603", Cap_Case=0603, Manufacturer=TDK, Supplier Part Number 1=445-6938-1-ND, TempCo=X7S, Tolerance_%=10%, Value1="0.04959 ohm", Value2=100V, ValueDisplayed=0.1uF
C15 C18: library part CMP-0007082-4, "CAP, CERM, 0.01 uF, 100 V, +/- 10%, X7R, AEC-Q200 Grade 1, 0603", Cap_Case=0603, Manufacturer=TDK, Supplier Part Number 1=445-5812-1-ND, TempCo=X7R, Tolerance_%=10%, Value1="0.235428 ohm", Value2=100V, ValueDisplayed=0.01uF
C16 C17: library part CMP-0006723-4, "CAP, CERM, 1000 pF, 100 V, +/- 5%, X7R, 0603", Cap_Case=0603, Manufacturer=AVX, Supplier Part Number 1=478-3698-1-ND, TempCo=X7R, Tolerance_%=5%, Value1="0.276 ohm", Value2=100V, ValueDisplayed=1000pF
C21 C22 C23: library part CMP-0083626-1, "CAP, CERM, 0.1 µF, 16 V,+/- 10%, X7R, AEC-Q200 Grade 1, 0603", Cap_Case=0603, Manufacturer=AVX, Supplier Part Number 1=478-9382-1-ND, TempCo=X7R, Tolerance_%=10%, Value2=16V, ValueDisplayed=0.1µF
D1: library part CMP-0002829-3, "LED, Red, SMD", Color=red, Manufacturer=Lite-On, Value1=W, Value2=2V
D2: library part CMP-0002888-2, "LED, Green, SMD", Color=Green, Manufacturer=Lite-On, Value1=W, Value2=2V
D3: library part CMP-0028882-2, "Diode, Schottky, 40 V, 0.75 A, AEC-Q101, SOD-323", Manufacturer="Infineon Technologies", Value1=0.75A, Value2=0.74V
D4: library part CMP-0078131-2, "LED, Red, SMD", Color=Red, Manufacturer=Lite-On, Power_TotalModule=62.5mW, Value1=.0625W, Value2=2V
D5: library part CMP-0002827-3, "LED, Green, SMD", Color=green, Manufacturer=Lite-On, Power_TotalModule=100mW, Value1=0.1W, Value2=2.1V
D6: library part CMP-0076979-3, "Diode, Switching, 100 V, 0.25 A, SOD-523", Manufacturer=Nexperia, Value1=0.25A, Value2=1.25V
FID1 FID2 FID3: library part CMP-0077181-1, "Fiducial mark.  There is nothing to buy or mount.", Manufacturer=N/A
H1 H2 H3 H4: library part CMP-0003617-1, "Machine Screw, Round, #4-40 x 1/4, Nylon, Philips panhead", Manufacturer="B&F Fastener Supply", Supplier Part Number 1=H542-ND
H5 H6 H7 H8: library part CMP-0003610-1, "Standoff, Hex, 0.5\"L #4-40 Nylon", Manufacturer=Keystone, PartNumber=1902C, Supplier Part Number 1=36-1902C-ND
J1 J3 J5 J13: library part CMP-0002334-1, "Header, 100mil, 3x1, Gold, TH", Manufacturer="Sullins Connector Solutions", PartNumber=PBC03SAAN, Supplier Part Number 1=S1011E-03-ND
J2: library part CMP-0055311-1, "Receptacle, USB 2.0, Micro B, 5 Position, R/A, SMT", Color=Black, Current_A=1.8A, Manufacturer=Molex, Supplier Part Number 1=WM11263CT-ND, Voltage_V=30V
J4: library part CMP-0075409-2, "Header, 100mil, 4x1, Gold, TH", Color=Black, Current_A=6.3A, Manufacturer=Samtec, Supplier Part Number 1=SAM1029-04-ND, Voltage_V=550V
J6: library part CMP-0075464-1, "Header, 100mil, 9x2, Gold, TH", Color=Black, Current_A=6.3A, Manufacturer=Samtec, Supplier Part Number 1=SAM1028-09-ND, Voltage_V=550V
J7 J12: library part CMP-0074911-1, "Terminal Block, 5.08 mm, 3x1, Brass, TH", Color=Blue, Current_A=15A, Manufacturer="On-Shore Technology", PartNumber=ED120/3DS, Supplier Part Number 1=ED1610-ND, Voltage_V=300V
J8 J9 J10: library part CMP-0002337-1, "Header, 100mil, 2x1, Tin, TH", Color=Black, Current_A=3A, Manufacturer="Sullins Connector Solutions", Supplier Part Number 1=S1012E-02-ND, Voltage_V=1.8kV
J11: library part CMP-0074957-2, "Terminal Block, 8x1, 3.5mm, TH", Manufacturer="On-Shore Technology", Supplier Part Number 1=ED2641-ND
L1: library part CMP-0084877-1, "Inductor, Ferrite Bead, Ferrite, 3 A, 120 ohm, AEC-Q200 Grade 1, SMD", Manufacturer=MuRata, Value1="120 ohm", Value2=3A
L2: library part CMP-0056795-1, "Inductor, Shielded, Powdered Iron, 1 uH, 18 A, 0.003 ohm, AEC-Q200 Grade 1, SMD", Manufacturer=Bourns, Supplier Part Number 1=SRP1038A-1R0MCT-ND, Value1="0.003 ohm", Value2=18A, ValueDisplayed=1uH
LBL1: library part CMP-0003625-1, Manufacturer=Brady, Supplier Part Number 1=97C5133
Logo1: library part CMP-0074844-1
Logo2: library part CMP-0074838-1, "Texas Instrument Corporate Signature"
Logo3: library part CMP-0074847-1, "FCC_disclaimer"
Logo4: library part CMP-0074769-3, Manufacturer="Texas Instruments"
LOGO5 LOGO6: library part CMP-0074837-2, "IEC 61010-1 Hot Surface Warning", Manufacturer="Texas Instruments"
NT1: library part CMP-0078142-6, "Single point connection between nets.", Manufacturer=N/A
Q1: library part CMP-0000467-2, "Transistor, NPN, 80 V, 1.5 A, AEC-Q101, SOT-23", Manufacturer="Diodes Inc.", Supplier Part Number 1=FMMT620CT-ND, Value1="1.5 A", Value2=900
Q2: library part CMP-0088880-1, "N-Channel 40V 8A (Ta) 15W (Tc) Surface Mount DFN2020MD-6", Digikey Part Number=1727-7413-1-ND, Drain To Source Breakdown Voltage=40V, Input Capacitace At Vds="637pF @ 20V", Manufacturer=Nexperia, Mouser Part Number=771-BUK9D23-40EX, Operating Temperature Range="-55°C to +175°C", Power_W=2.3W, Pulse Drain Current=76A, Typ Forward Diode Voltage=0.8V
R1 R2 R4 R5 R27 R28 R29 R30 R31: library part CMP-0022746-5, "RES, 10.0 k, 1%, 0.1 W, 0603", Manufacturer=Yageo, Power_W=100mW, Supplier Part Number 1=311-10.0KHRCT-ND, TempCo="100 ppm/C", Tolerance_%=1%, Value2=0.1W, Value_Code=10k0, ValueDisplayed=10.0k
R3 R10 R11 R12 R13 R14 R17 R21 R22: library part CMP-0025874-4, "RES, 0, 5%, 0.1 W, AEC-Q200 Grade 0, 0603", Manufacturer=Panasonic, Power_W=100mW, Supplier Part Number 1=P0.0GCT-ND, TempCo="600 ppm/C", Tolerance_%=5%, Value2=0.1W, Value_Code=0000, ValueDisplayed=0
R6: library part CMP-0001776-2, "Trimmer Potentiometer, 25kohm, 0.5W, TH", Manufacturer=Bourns, Supplier Part Number 1=3352T-253LF-ND
R7 R8 R33: library part CMP-0025932-5, "RES, 5.1 k, 5%, 0.1 W, 0603", Manufacturer=Yageo, Power_W=100mW, Supplier Part Number 1=311-5.1KGRCT-ND, TempCo="100 ppm/C", Tolerance_%=5%, Value2=0.1W, Value_Code=5k10, ValueDisplayed=5.1k
R9: library part CMP-0093882-3, "10 kOhms 0.5W, 1/2W Through Hole Thumbwheel Potentiometer Top Adjustment", Digikey Part Number=3352T-103LF-ND, Manufacturer=Bourns, Mouser Part Number=652-3352T-1-103LF, Operating Temperature Range="-55°C to +125°C", Power=500mW, Power_W=0.5W, TempCo=100ppm/°C, Tolerance_%=20%, Voltage=250V
R15: library part CMP-0025937-5, "RES, 6.2 k, 5%, 0.1 W, 0603", Manufacturer=Yageo, Power_W=100mW, Supplier Part Number 1=311-6.2KGRCT-ND, TempCo="100 ppm/C", Tolerance_%=5%, Value2=0.1W, Value_Code=6k20, ValueDisplayed=6.2k
R16 R23: library part CMP-0023363-3, "RES, 100 k, 0.1%, 0.1 W, AEC-Q200 Grade 0, 0603", Manufacturer=Panasonic, Power_W=100mW, Supplier Part Number 1=P100KDBCT-ND, TempCo="25 ppm/C", Tolerance_%=0.1%, Value2=0.1W, Value_Code=100k
R18: library part CMP-0022692-3, "RES, 22.0 k, 1%, 0.1 W, AEC-Q200 Grade 0, 0603", Manufacturer=Panasonic, Power_W=100mW, Supplier Part Number 1=P22.0KHCT-ND, TempCo="100 ppm/C", Tolerance_%=1%, Value2=0.1W, Value_Code=22k0, ValueDisplayed=22.0k
R19: library part CMP-0025899-5, "RES, 1.0 k, 5%, 0.1 W, 0603", Manufacturer=Yageo, Power_W=100mW, Supplier Part Number 1=311-1.0KGRCT-ND, TempCo="100 ppm/C", Tolerance_%=5%, Value2=0.1W, Value_Code=1k00, ValueDisplayed=1.0k
R20: library part CMP-0024300-2, "RES, 4.70 k, 0.1%, 0.1 W, 0603", Manufacturer="Yageo America", Power_W=100mW, TempCo="25 ppm/C", Tolerance_%=0.1%, Value2=0.1W, Value_Code=4k70, ValueDisplayed=4.70k
R24: library part CMP-0025925-5, "RES, 47 k, 5%, 0.1 W, 0603", Manufacturer=Yageo, Power_W=100mW, Supplier Part Number 1=311-47KGRCT-ND, TempCo="100 ppm/C", Tolerance_%=5%, Value2=0.1W, Value_Code=47k0, ValueDisplayed=47k
R25 R26: library part CMP-0025924-5, "RES, 470, 5%, 0.1 W, 0603", Manufacturer=Yageo, Power_W=100mW, Supplier Part Number 1=311-470GRCT-ND, TempCo="100 ppm/C", Tolerance_%=5%, Value2=0.1W, Value_Code=470R, ValueDisplayed=470
R32: library part CMP-0018760-2, "RES, 0, 5%, 0.25 W, AEC-Q200 Grade 0, 1206", Manufacturer=Vishay-Dale, Power_W=250mW, Supplier Part Number 1=541-2239-1-ND, TempCo=ppm/C, Tolerance_%=5%, Value2=0.25W, Value_Code=0000, ValueDisplayed=0
S1 S2: library part CMP-0002155-2, "SWITCH TOGGLE SPDT 0.4VA 28V", CurrentRating_mA=100A, Manufacturer="NKK Switches", PartNumber=B12AP, Supplier Part Number 1=360-1012-ND
S3: library part CMP-0002196-2, "Switch, Tactile, SPST, 12 V, SMD", CurrentRating_mA=50A, Manufacturer="Wurth Elektronik", PartNumber=434121025816, Supplier Part Number 1=31T8978
SH-J1 SH-J2 SH-J3 SH-J4 SH-J5 SH-J6 SH-J7 SH-J8 SH-J9 SH-J10 SH-J11 SH-J12 SH-J13 SH-J14 SH-J15 SH-J16: library part CMP-0003623-3, "Shunt, 100mil, Gold plated, Black", Alternate Manufacturer=3M, Alternate PartNumber=969102-0000-DA, Manufacturer=Samtec, Supplier Part Number 1=SAM8858-ND
TP1 TP2 TP3 TP4 TP8 TP9 TP21 TP22 TP27 TP28 TP29 TP30: library part CMP-0055139-2, "Test Point, Miniature, White, TH", Color=White, Manufacturer="Keystone Electronics", PartNumber=5002, Supplier Part Number 1=36-5002-ND
TP5 TP6 TP7 TP10 TP11 TP12 TP13 TP14 TP26 TP31: library part CMP-0055137-2, "Test Point, Miniature, Red, TH", Color=Red, Manufacturer="Keystone Electronics", PartNumber=5000, Supplier Part Number 1=36-5000-ND
TP15 TP16: library part CMP-0055142-2, "Test Point, Compact, Red, TH", Color=Red, Manufacturer="Keystone Electronics", PartNumber=5005, Supplier Part Number 1=36-5005-ND
TP17 TP23 TP24 TP25: library part CMP-0055138-2, "Test Point, Miniature, Black, TH", Color=Black, Manufacturer="Keystone Electronics", PartNumber=5001, Supplier Part Number 1=36-5001-ND
TP18 TP19 TP20: library part CMP-0075110-1, "1mm Uninsulated Shorting Plug, 10.16mm spacing, TH", Manufacturer=Harwin, PartNumber=D3082-05, Supplier Part Number 1=952-1873-ND
U1: library part CMP-0034379-1, Manufacturer="Texas Instruments", Operating Temperature Range=to
U2: library part CMP-0121693-1, "UART Interface IC USB Full Speed to Serial UART IC, Includes Oscillator and EEPROM, SSOP-28", Digikey Part Number=768-FT232RNL-REELCT-ND, Manufacturer=FTDI, Max Supply Voltage=5.25V, Min Supply Voltage=1.8V, Mouser Part Number=895-FT232RNL-REEL, Nominal Supply Current=7mA, Operating Temperature Range="-40°C to +85°C"
U3: library part CMP-0043115-3, "4-Channel ESD Protection Array for High-Speed Data Interfaces, DRY0006A (USON-6)", Breakdown Voltage(Min)(V)=6, IO Capacitance(Typ)(pF)=1.6, IO Leakage Current(nA)=1, Manufacturer="Texas Instruments", Operating Temperature Range="-40 to 85 C", Rating=Catalog
U4: library part CMP-0089204-1, "CPU16 MSP430™ FRAM Microcontroller IC 16-Bit 24MHz 32KB (32K x 8) FRAM 48-LQFP (7x7)", Digikey Part Number=296-50261-1-ND, Frequency_Fixed=24MHz, Manufacturer="Texas Instruments", Max Supply Voltage=3.6V, Min Supply Voltage=1.8V, Mouser Part Number=595-MSP430FR2355TPTR, Operating Temperature Range="-40°C to +105°C"
Y1: library part CMP-0084387-1, "Resonator, 4 MHz, 39 pF, AEC-Q200 Grade 1, SMD", Frequency_Fixed=4MHz, Load Capacitance="39 pF", Manufacturer=MuRata
ZZ1: library part CMP-0003616-3
ZZ2: library part CMP-0077236-1
ZZ3: library part CMP-0077237-1
ZZ4: library part CMP-0077238-1

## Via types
v1: diameter 20, hole 10, Top Layer to Bottom Layer, tented both sides, 341 vias
v2: diameter 20, hole 10, Top Layer to Bottom Layer, 31 vias
v3: diameter 19.68, hole 7.87, Top Layer to Bottom Layer, tented both sides, 5 vias

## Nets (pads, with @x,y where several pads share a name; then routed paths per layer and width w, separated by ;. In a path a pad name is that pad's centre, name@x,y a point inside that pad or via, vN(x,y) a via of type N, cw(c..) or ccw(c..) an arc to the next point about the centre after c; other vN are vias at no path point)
3V3_MCU: C11.1 D1.1 D3.1 J4.2 J5.2 R6.1 R7.2 R8.2 R24.2 R25.2 R26.2 R33.2 TP14.1 U4.6 | length 3093.7
  Top Layer w10: R6.1@115,2100 217.5,1997.5 217.5,1672.34 R24.2@404.76,1485.08 404.76,1484.09 v2(443.86,1445) ; 605,1246.18 U4.6@676.9,1246.18 731.55,1246.18 v2(731.68,1246.32) ; v2(1120.21,1202.5) 1131.97,1214.26 R26.2@1163.95,1214.26 ; v2(1120.21,1352.5) R25.2@1163.95,1352.5 ; v1(2154.27,1456.84) 2197.08,1456.84 R7.2@2197.93,1457.69 ; v1(2200.05,1535.24) R33.2@2200.05,1575.28
  Top Layer w20: C11.1@561.16,1246.18 605,1246.18 ; D3.1@1213.31,447.36 TP14.1@1213.31,563.23 ; v1@2200.55,1991.48 R8.2@2240.61,1991.48 2240.99,1991.86 2240.99,2097.29 D1.1@2241.38,2097.68
  Power w20: v2(1120.21,1202.5) 1899.93,1202.5 v1(2154.27,1456.84) 2200.05,1502.61 v1(2200.05,1535.24) v1(2200.05,1991.48)
3V3COM: C7.1 D3.2 J5.3 TP10.1 U2.4 U2.17 | length 1452.3
  Top Layer w10: C7.1@810.02,967.5 C7.1@811,967.5 ; J5.3@1437.11,137.5 J5.3@1442.5,137.5
  Top Layer w15: U2.17@572.34,609.17 572.34,686.63 635.71,750 734.91,750 777.07,792.16 777.07,880.83 777.07,934.55 C7.1@810.02,967.5
  Top Layer w20: 777.07,792.16 TP10.1@1005.39,563.83 1010.22,563.83 D3.2@1126.69,447.36 ; D3.2@1126.97,447.64 J5.3@1437.11,137.5
3V3EXT: J5.1 TP13.1 | length 514.2
  Top Layer w10: TP13.1@1195,131.31 TP13.1@1195,137.5
  Top Layer w20: TP13.1@1195,131.31 1264.93,61.38 1566.38,61.38 J5.1@1642.5,137.5
5V_EXT: J3.1 TP12.1 | length 224.1
  Top Layer w20: J3.1@780.89,137.5 TP12.1@1005.02,137.5
5V_USB: C6.1 J3.3 L1.1 TP11.1 U3.6 | length 470.5
  Top Layer w10: v1(415,585) 419.49,589.49 U3.6@435.35,589.49
  Top Layer w30: 380,502.56 580.89,301.68 J3.3@580.89,137.5
  other v1: 374.4,520 374.4,554.09 355.28,597.5
5VCC: C8.2 C9.1 J3.2 U2.20 | length 481.5
  Top Layer w10: C9.1@680.89,464.71 C9.1@681,464.83
  Top Layer w16: C8.2@625.49,464.83 625.49,465.81 649.11,489.43 U2.20@649.11,609.17
  Top Layer w25: J3.2@680.89,137.5 C9.1@680.89,464.71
